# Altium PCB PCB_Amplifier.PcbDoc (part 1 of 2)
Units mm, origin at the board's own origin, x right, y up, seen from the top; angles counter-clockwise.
Board outline 88.51 x 102.08 mm, 4 copper layers (Top Layer, GND, VDD, Bottom Layer); 234 components, 166 nets, 733 pads, 363 vias.
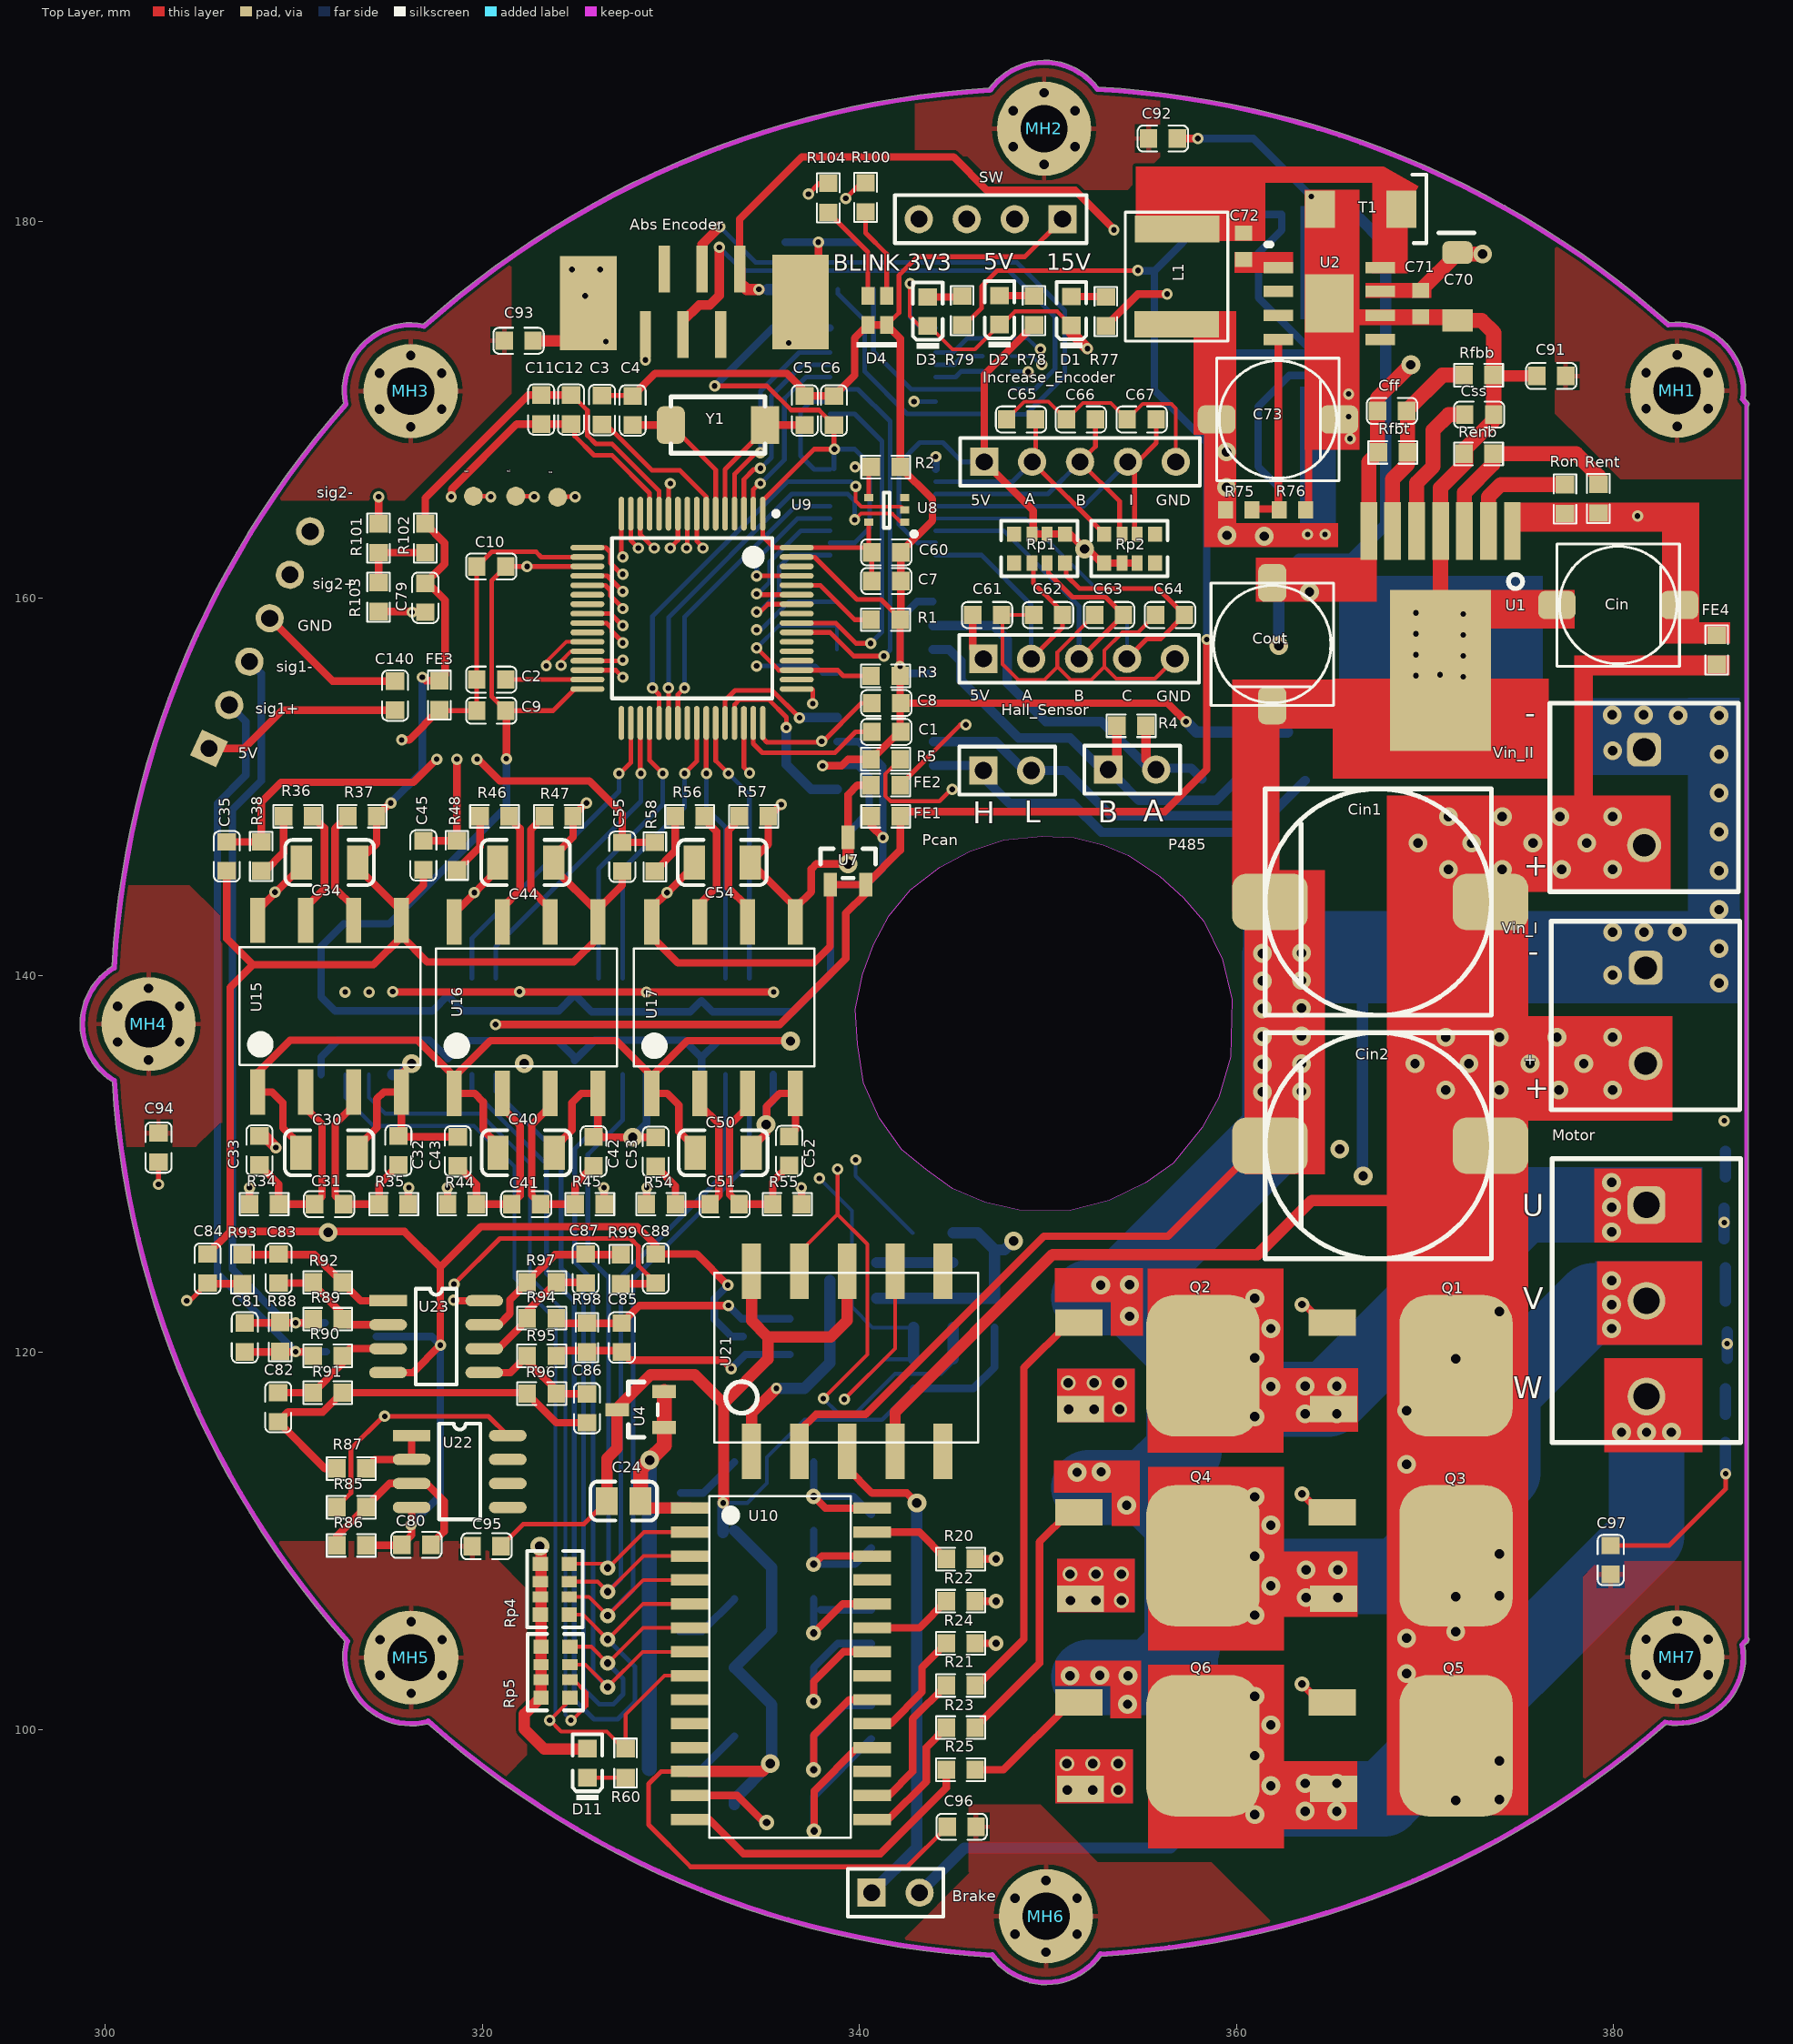
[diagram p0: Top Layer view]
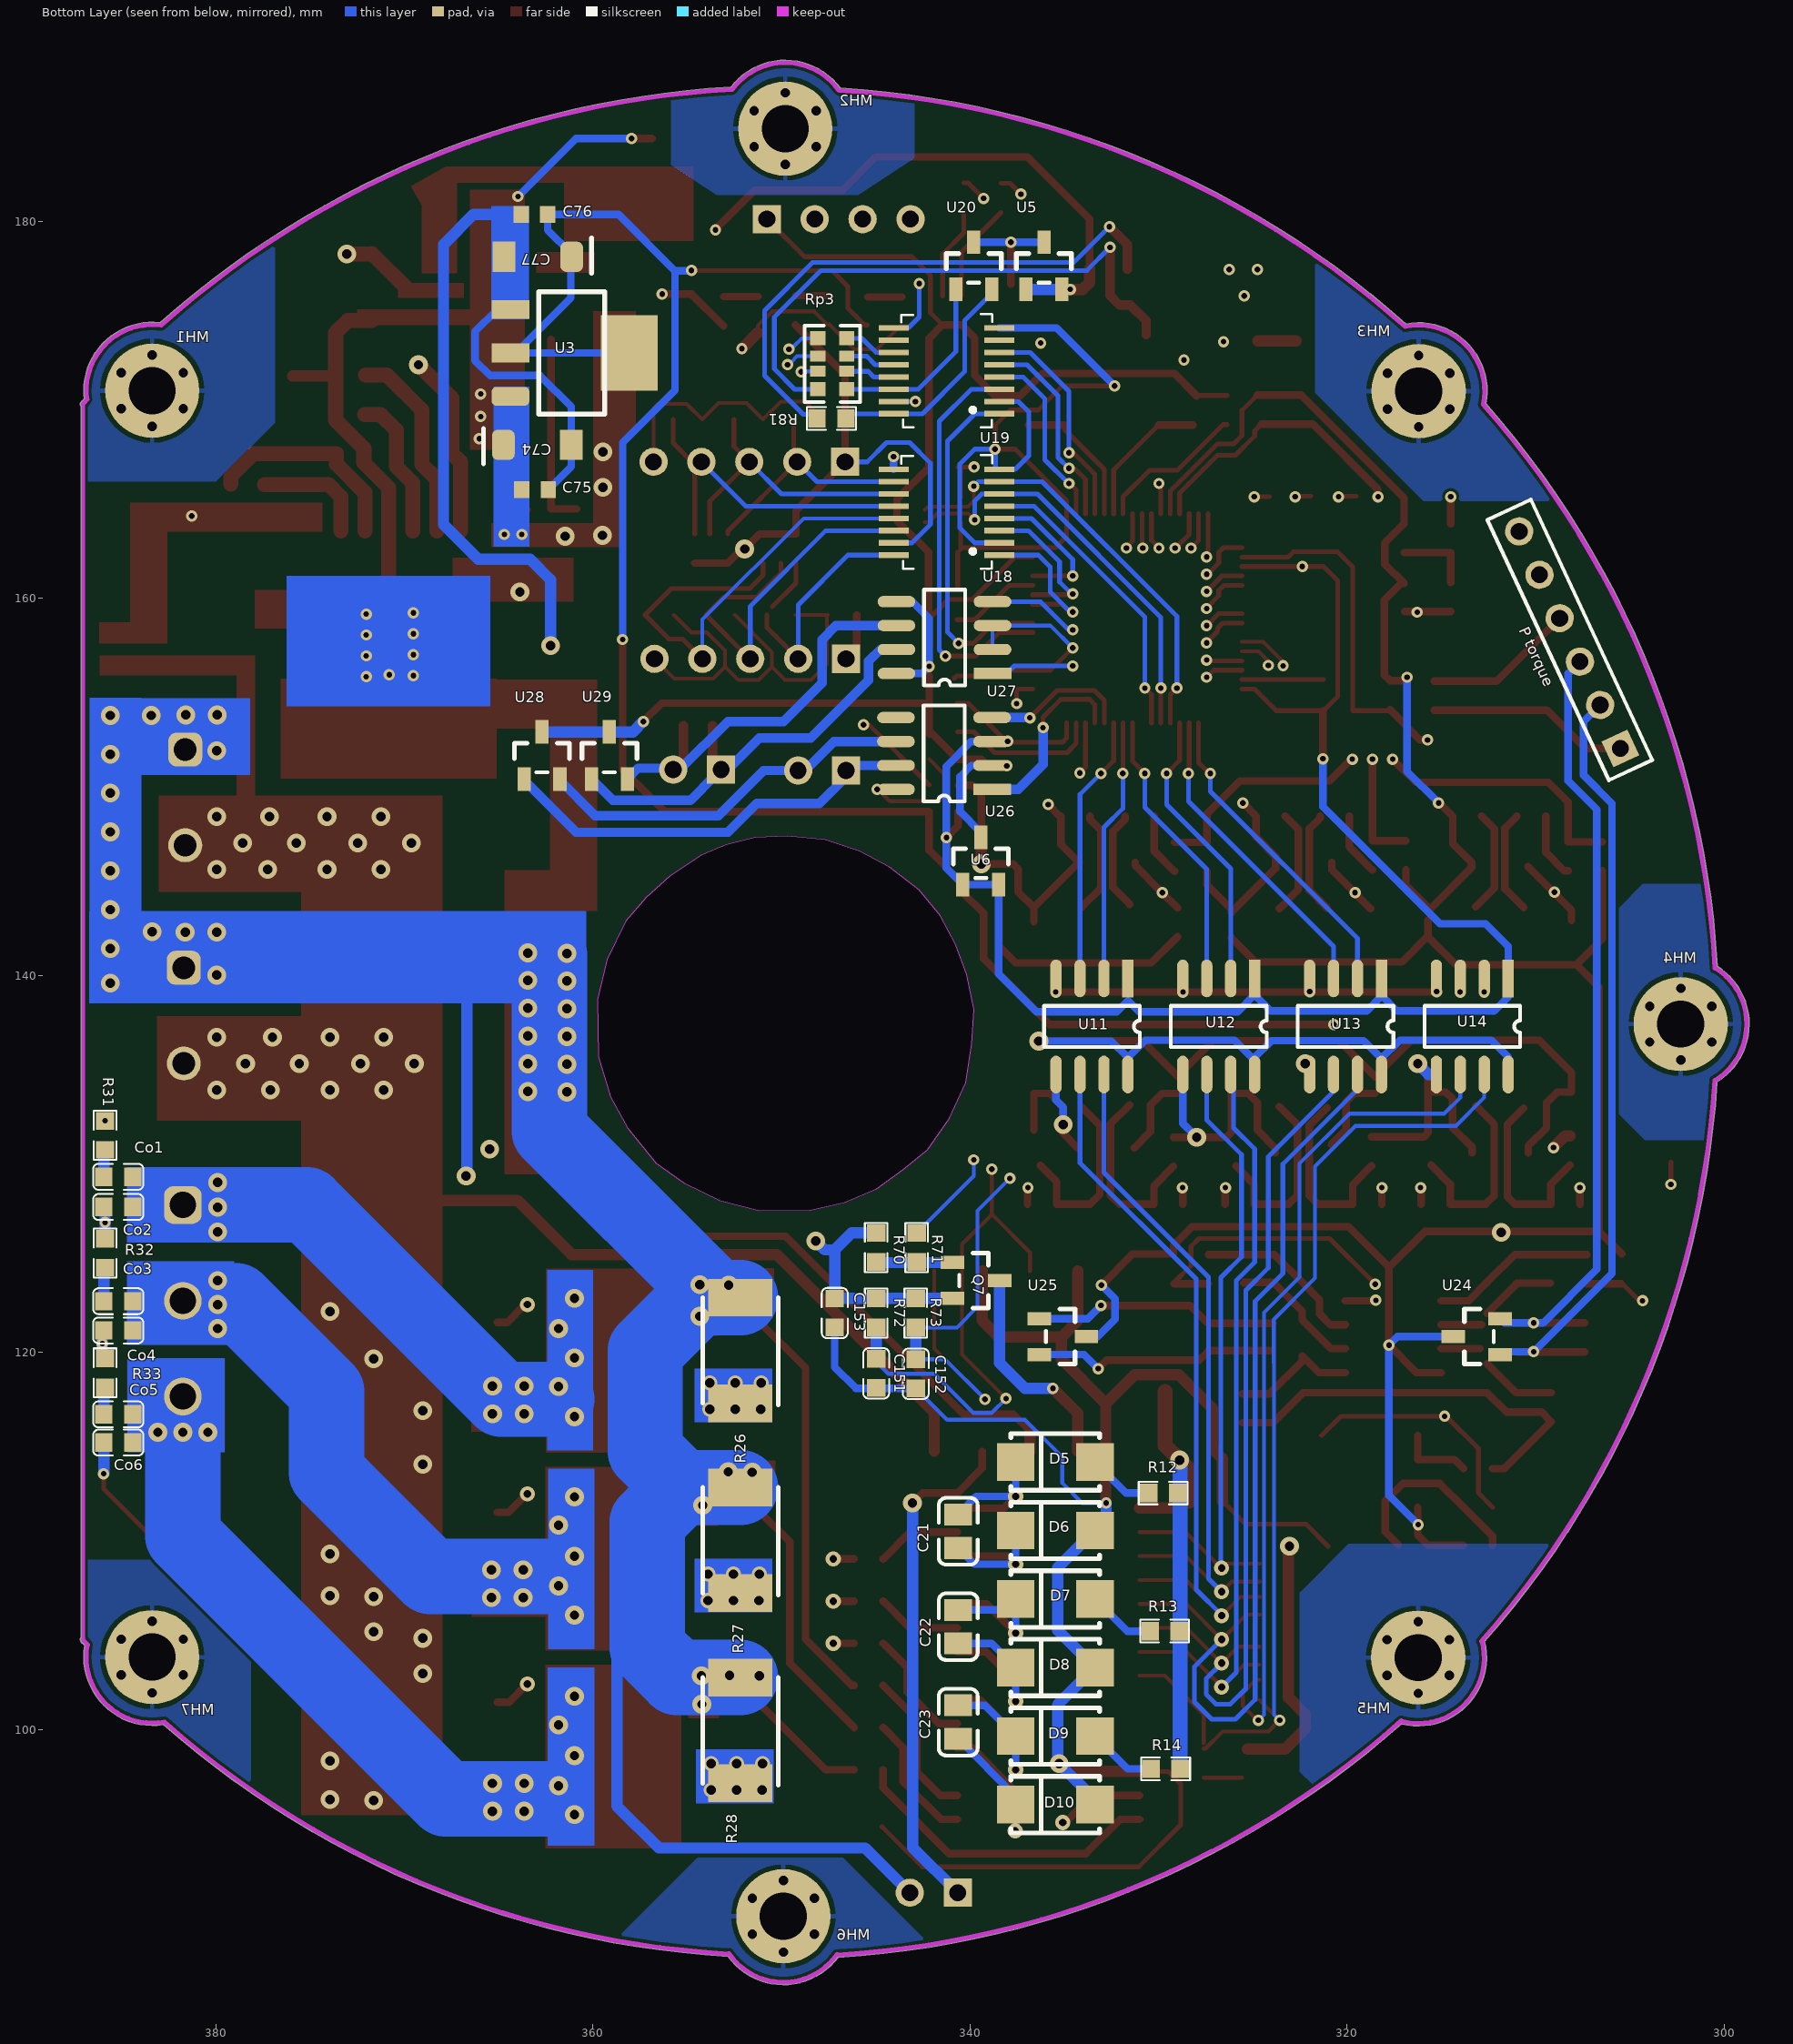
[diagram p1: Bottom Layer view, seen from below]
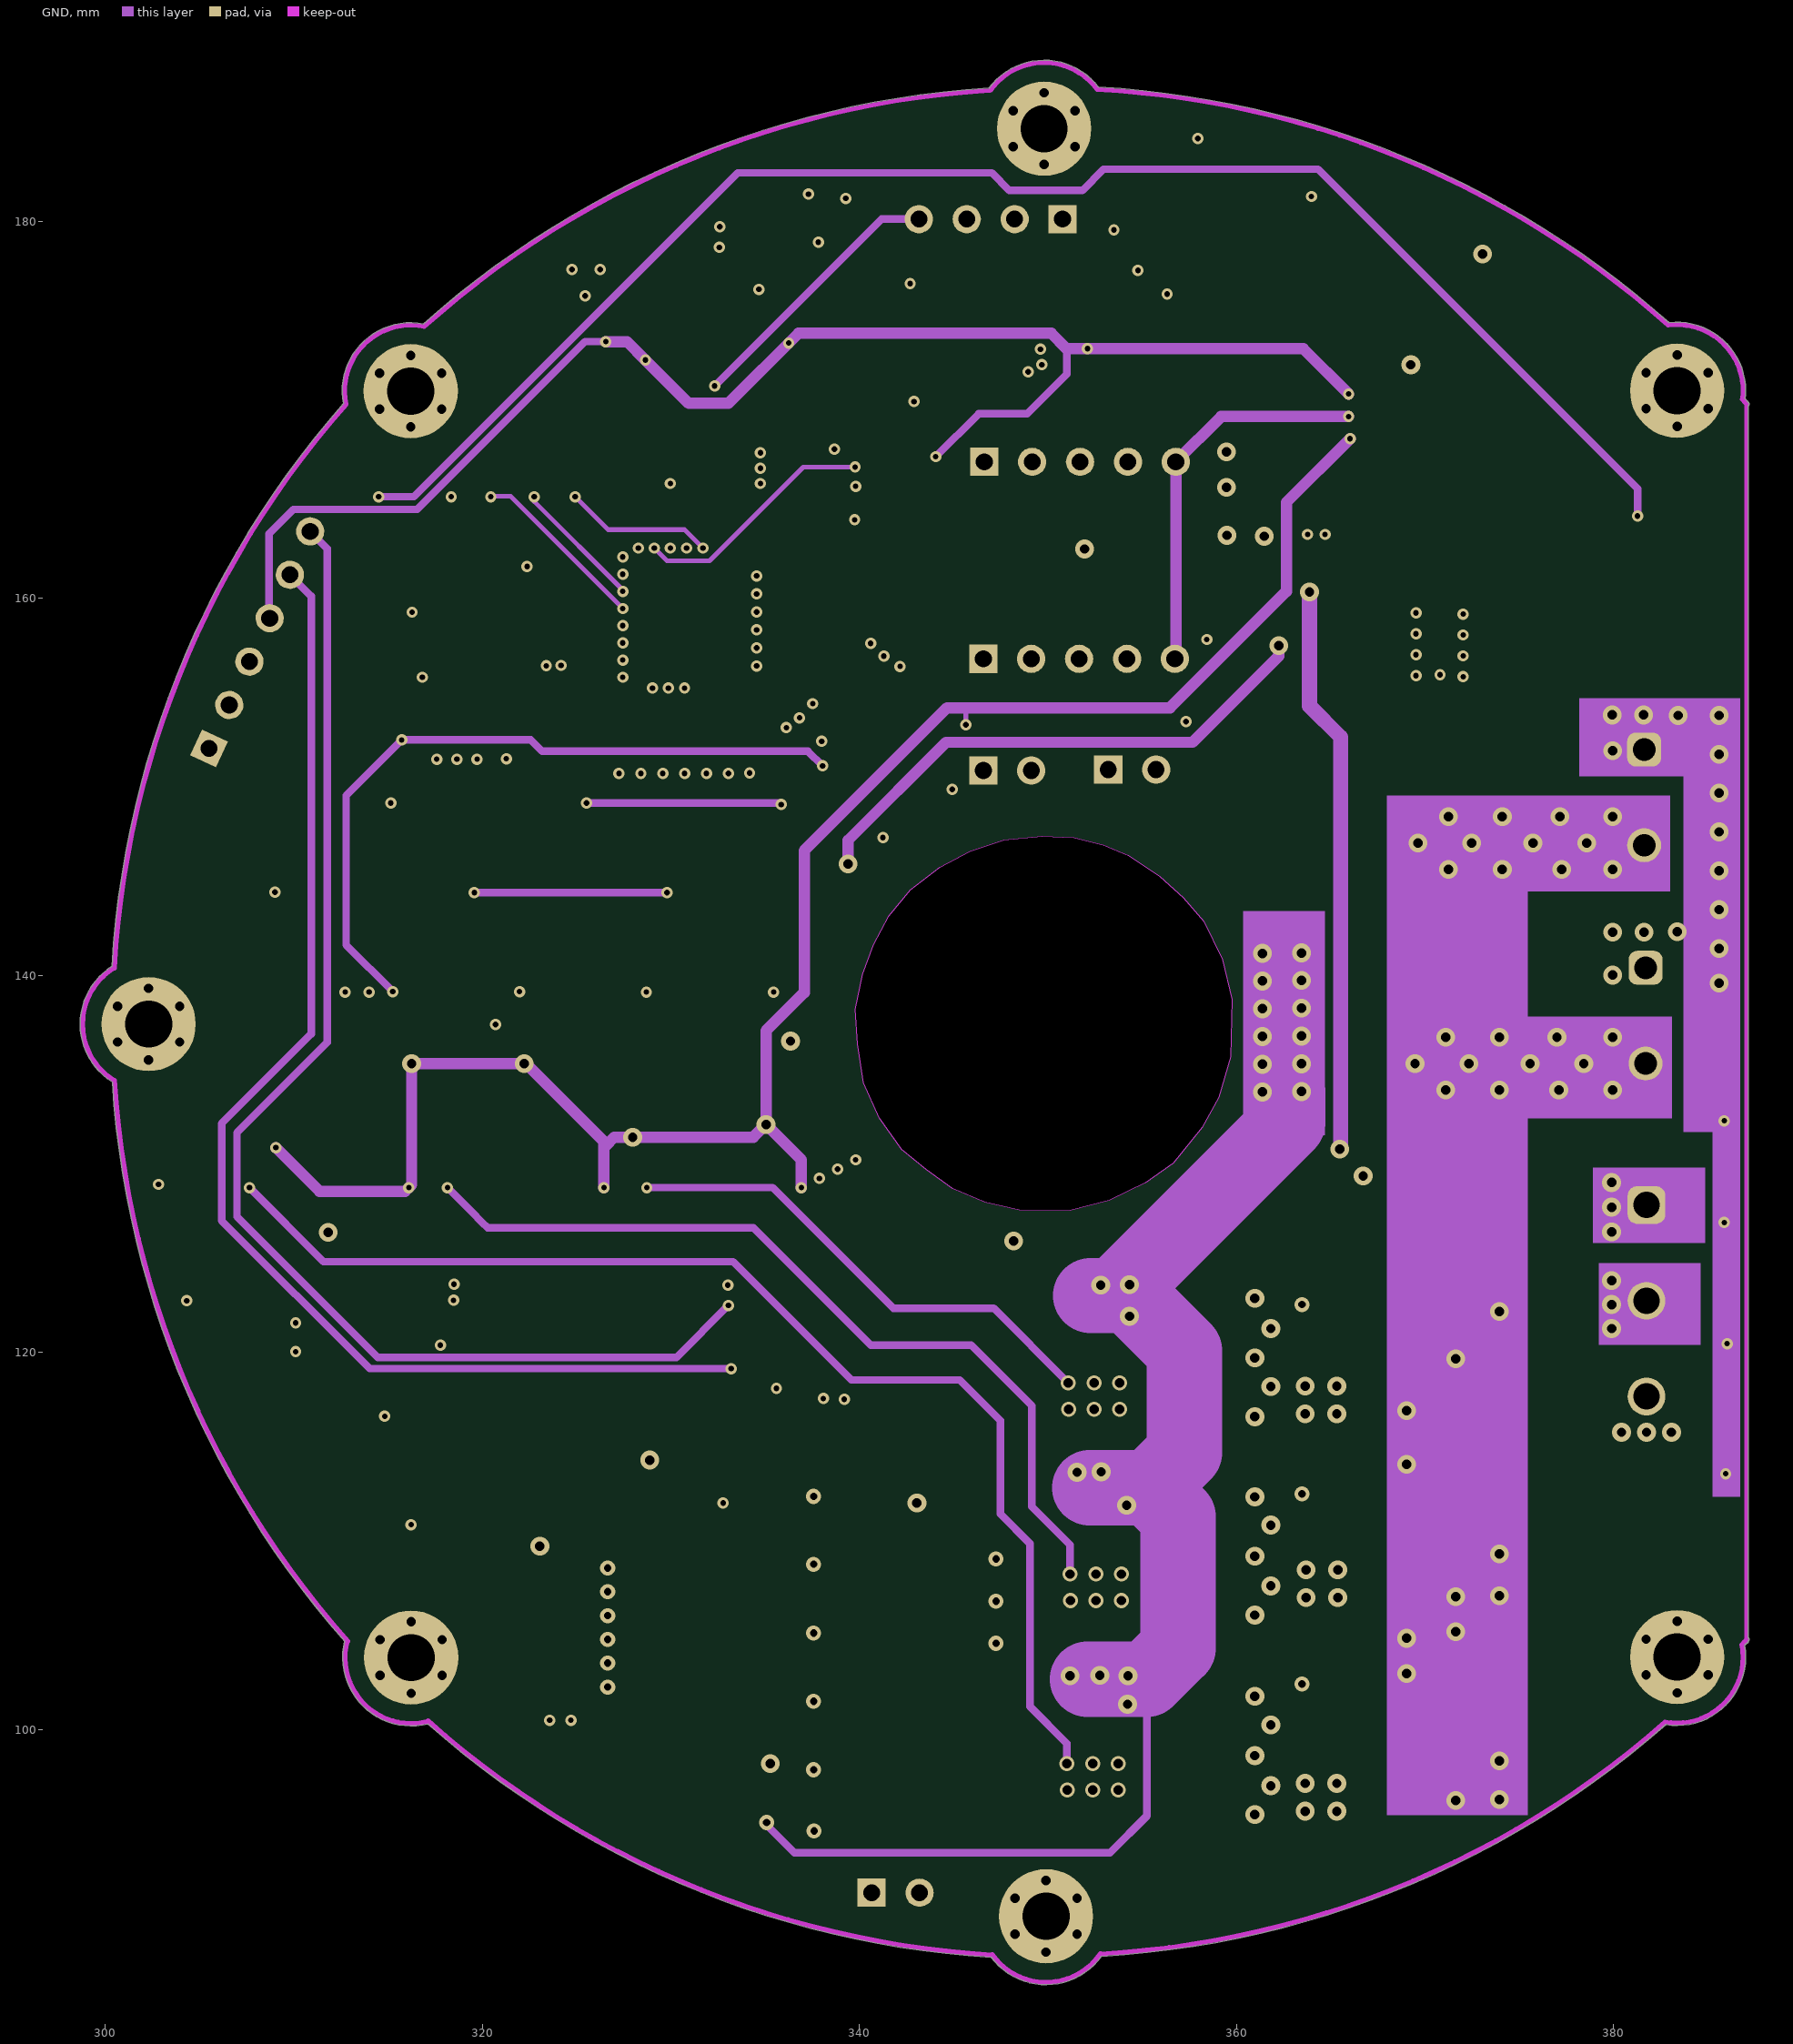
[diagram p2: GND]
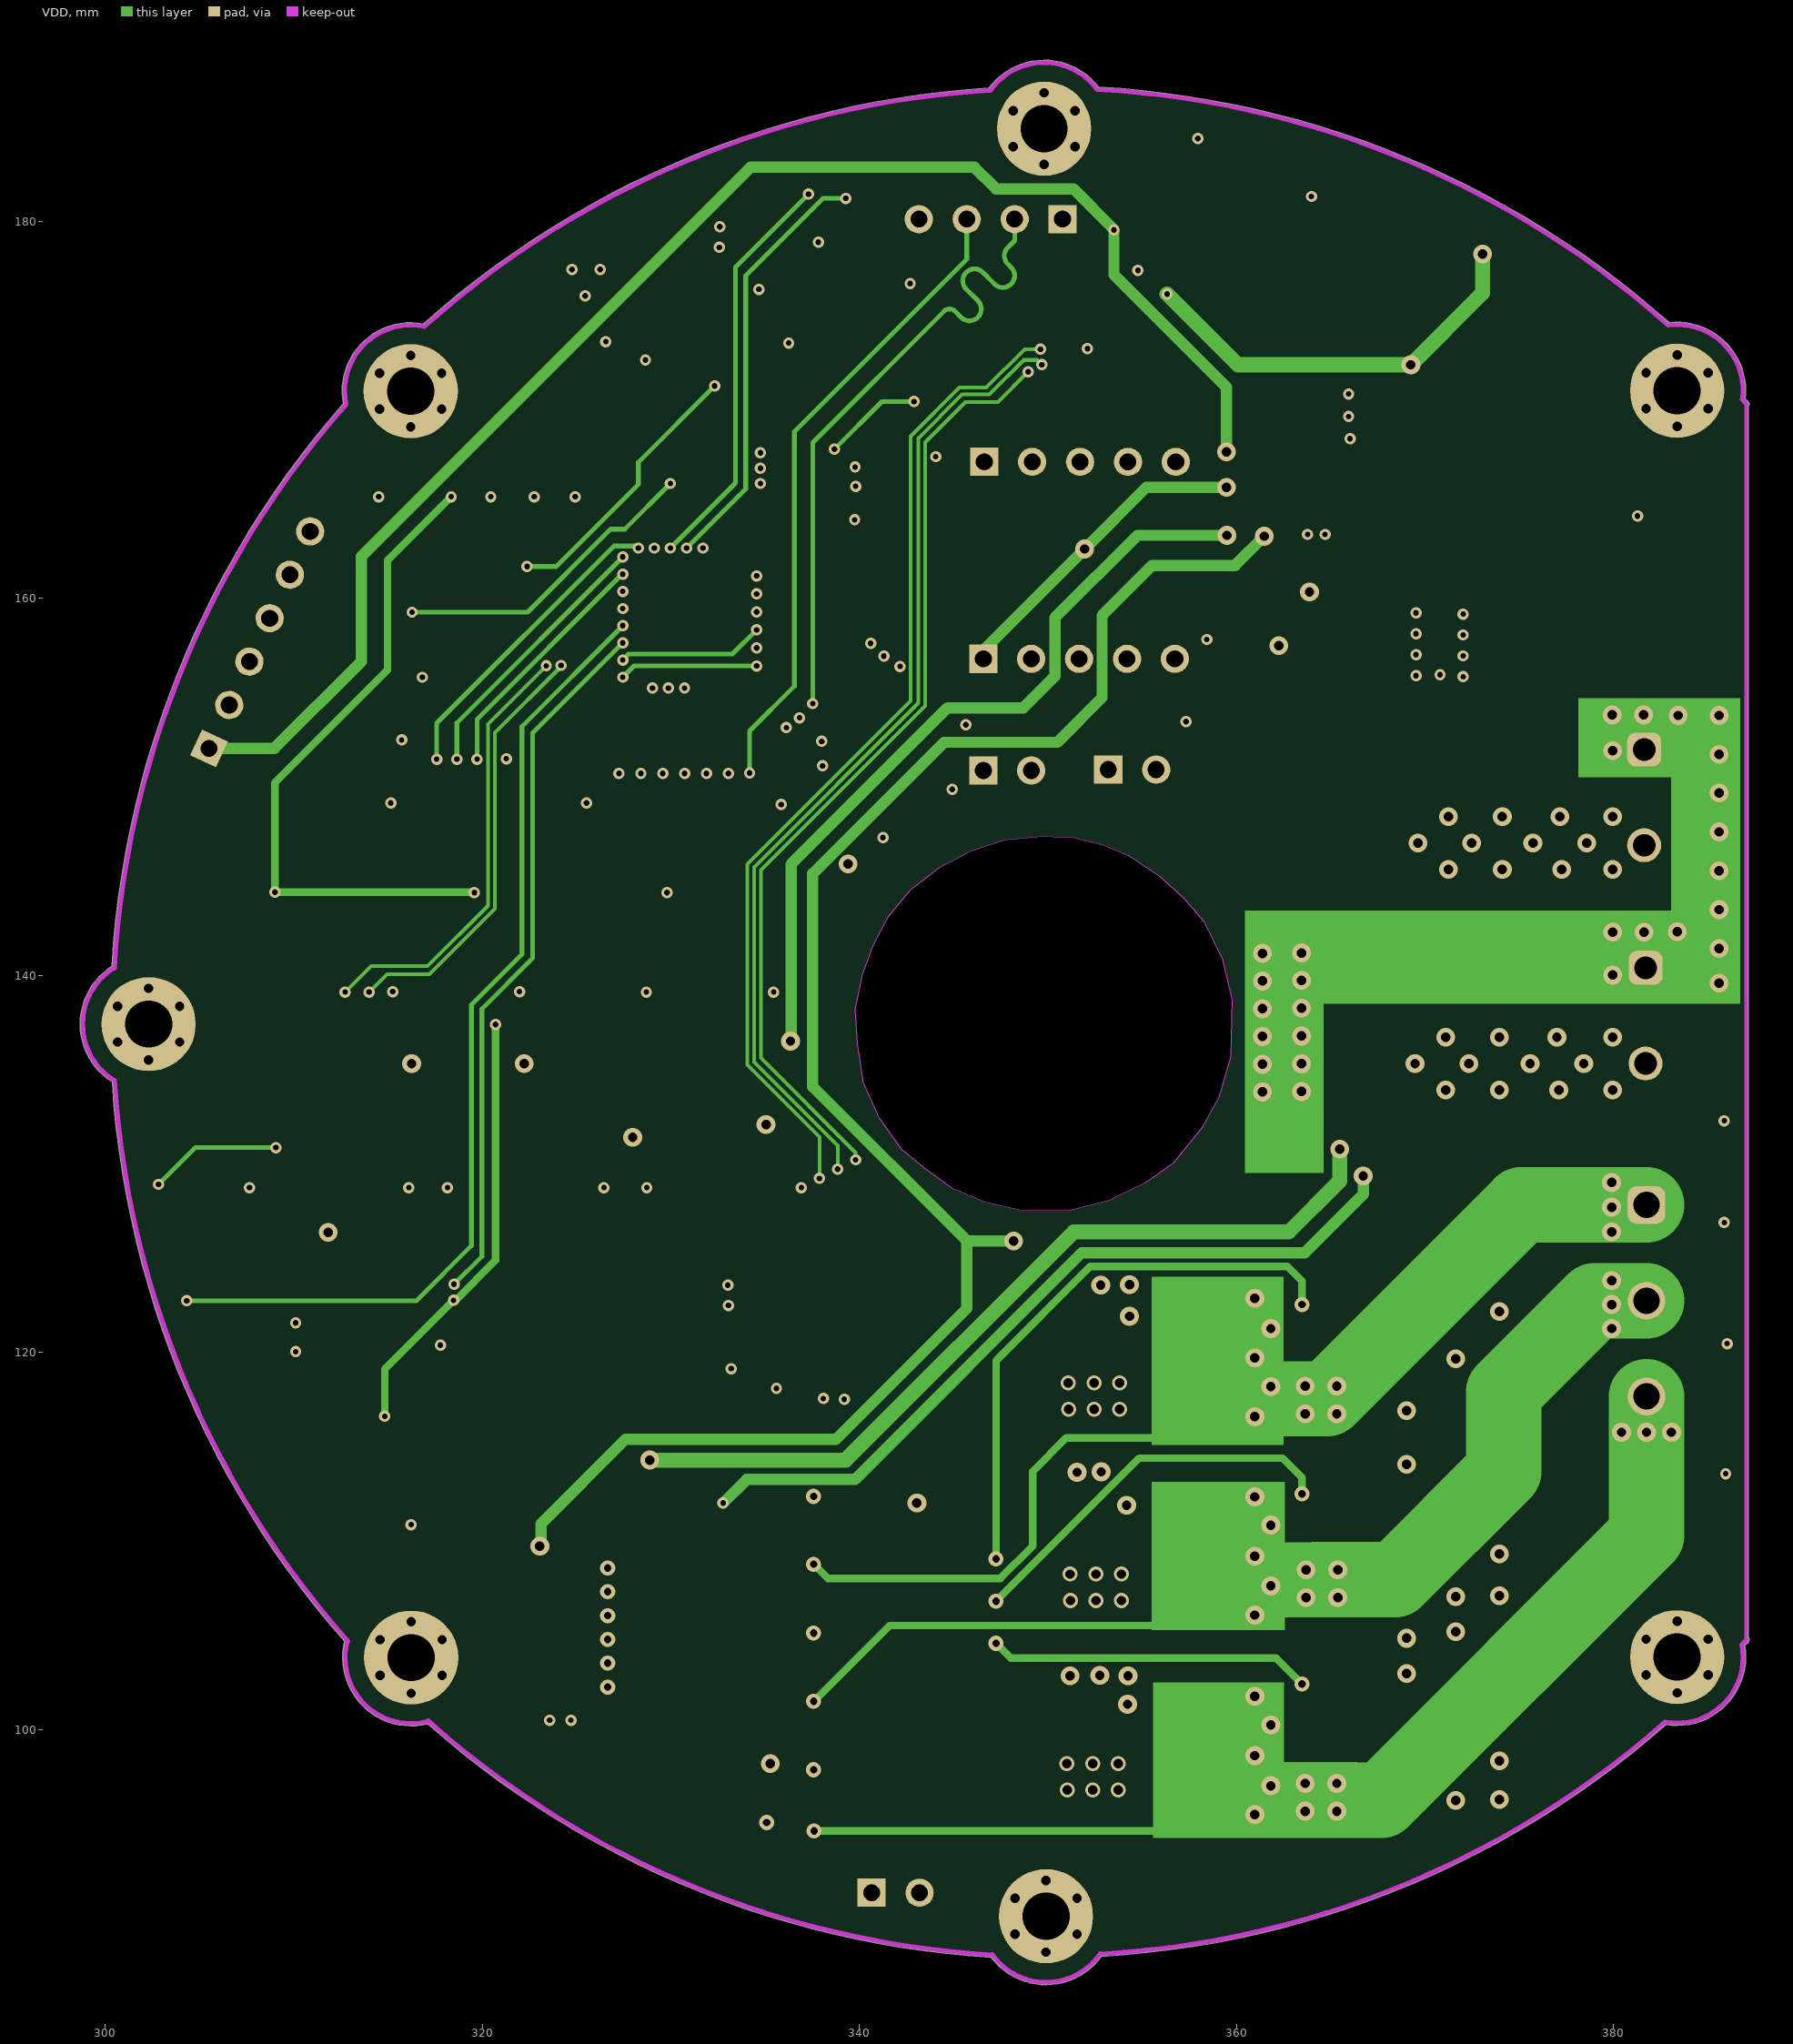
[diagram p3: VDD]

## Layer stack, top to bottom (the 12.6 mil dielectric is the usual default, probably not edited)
Top Layer: signal copper 0.0356
Dielectric: core 0.32, FR-4, Dk 4.8
GND: signal copper 0.0356
Dielectric: prepreg 0.32, FR-4, Dk 4.8
VDD: signal copper 0.0356
Dielectric: core 0.32, FR-4, Dk 4.8
Bottom Layer: signal copper 0.0356

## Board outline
317.109,100.307 ccw(c350.02,137.484) 346.997,87.925 ccw(c349.9,90.1) 352.843,87.979 ccw(c349.983,137.549) 382.781,100.272 ccw(c383.375,103.85) 387.002,103.85 ccw(c383.375,103.85) 386.949,104.467 ccw(c349.925,137.55) 387.049,104.579 ccw(c387.048,104.68) 387.148,104.68 387.148,104.691 ccw(c349.925,137.55) 387.158,104.703 ccw(c387.063,104.787) 387.19,104.787 ccw(c387.063,104.787) 387.148,104.881 387.148,170.219 ccw(c387.063,170.313) 387.19,170.313 ccw(c387.063,170.313) 387.158,170.397 ccw(c349.925,137.55) 387.141,170.418 ccw(c387.048,170.379) 387.098,170.466 ccw(c349.925,137.55) 386.978,170.601 ccw(c383.375,171.025) 387.002,171.025 ccw(c383.375,171.025) 382.949,174.627 ccw(c349.925,137.55) 352.684,187.125 ccw(c349.8,184.925) 346.88,187.077 ccw(c349.941,137.519) 316.879,174.563 ccw(c316.2,171) 312.635,170.333 ccw(c349.925,137.55) 300.36,140.49 ccw(c302.3,137.425) 300.377,134.35 ccw(c349.925,137.55) 312.702,104.69 ccw(c316.225,103.825)
cut-out: 349.675,147.4 351.4,147.325 352.925,146.925 354.25,146.375 355.925,145.275 357.175,144.125 358.275,142.875 359.25,140.85 359.75,138.725 359.7,135.7 359.05,133.55 358.175,131.925 356.65,130.05 355.175,129 353.25,128.075 351.175,127.525 348.475,127.55 346.65,127.975 344.95,128.7 343.55,129.7 342.25,130.775 341.075,132.425 340.225,134.325 339.9,136.375 339.775,138.2 340.175,140.05 340.75,141.625 341.575,143.175 342.7,144.55 344.275,145.75 345.875,146.6 347.675,147.2

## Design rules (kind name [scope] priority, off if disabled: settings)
Clearance [All] p1: gap=0.16
PolygonConnect [All] p1: connectstyle=Relief reliefconductorwidth=0.254 reliefentries=4 polygonreliefangle="90 Angle" airgapwidth=0.254
RoutingVias [All] p1: holewidth=0.711 width=1.27 viastyle="Through Hole" minholewidth=0.711 minwidth=1.27 maxholewidth=0.711 maxwidth=1.27
SolderMaskExpansion [All] p1: expansion=0.102
Width [All] p1: maxlimit=4 minlimit=0.2 preferedwidth=0.3
28 further rules are at their usual default settings.

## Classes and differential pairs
component class 电源: C70 C71 C72 C73 C74 C75 C76 C77 Cff Cin Cin1 Cin2 Cout Css D1 D2 D3 FE1 FE2 FE3 FE4 L1 R75 R76 R77 R78 R79 Renb Rent Rfbb Rfbt Ron T1 U1 U2 U3 U4 U5 U6 U7 Vin_I Vin_II
component class H桥驱动部分: C21 C22 C23 C24 C30 C31 C32 C33 C34 C35 C40 C41 C42 C43 C44 C45 C50 C51 C52 C53 C54 C55 Co1 Co2 Co3 Co4 Co5 Co6 D5 D6 D7 D8 D9 D10 D11 Motor Q1 Q2 Q3 Q4 Q5 Q6 R12 R13 R14 R20 R21 R22 R23 R24 R25 R26 R27 R28 R31 R32 R33 R34 R35 R36 R37 R38 R44 R45 R46 R47 R48 R54 R55 R56 R57 R58 R60 Rp4 Rp5 U10 U11 U12 U13 U14 U15 U16 U17
component class 主控芯片: C1 C2 C3 C4 C5 C6 C7 C8 C9 C10 C11 C12 C79 D4 R1 R2 R100 R101 R102 R103 R104 SW tp1 tp2 tp3 U8 U9 Y1
component class 通讯接口: P485 Pcan R3 R4 R5 U26 U27 U28 U29
component class 霍尔传感器以及增量编码器: C60 C61 C62 C63 C64 C65 C66 C67 C91 C92 C93 C94 C95 C96 C97 Hall_Sensor Increase_Encoder MH1 MH2 MH3 MH4 MH5 MH6 MH7 Rp1 Rp2 U18
component class 绝对编码器与抱闸: "Abs Encoder" Brake C151 C152 C153 Q7 R70 R71 R72 R73 R81 Rp3 U19 U20 U21
component class 外接力矩传感器接口: C80 C81 C82 C83 C84 C85 C86 C87 C88 C140 "P torque" R85 R86 R87 R88 R89 R90 R91 R92 R93 R94 R95 R96 R97 R98 R99 U22 U23 U24 U25

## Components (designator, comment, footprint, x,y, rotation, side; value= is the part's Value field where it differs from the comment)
"Abs Encoder" "7pin FFC" "FPC Con 6pin 1mm" 333.65,177.15 r270 top
Brake "Header 2" HDR1X2 340.65,91.35 r0 top
C1 "2.2uF (225) 10% 16V" 0603_C 341.425,152.925 r180 top
C2 "2.2uF (225) 10% 16V" 0603_C 320.475,155.7 r0 top
C3 "2.2uF (225) 10% 16V" 0603_C 326.35,170 r90 top
C4 "6pF (6R0) 0.25pF 50V" 0603_C 327.975,169.975 r90 top
C5 "6pF (6R0) 0.25pF 50V" 0603_C 337.1,169.975 r90 top
C6 "10uF (106) 10% 10V" 0603_C 338.65,169.975 r270 top
C7 "1uF (105) 10% 50V" 0603_C 341.425,160.925 r180 top
C8 "100nF (104) 10% 50V" 0603_C 341.425,154.45 r180 top
C9 "100nF (104) 10% 50V" 0603_C 320.475,154.05 r0 top
C10 "100nF (104) 10% 50V" 0603_C 320.475,161.7 r0 top
C11 "100nF (104) 10% 50V" 0603_C 323.125,170.025 r270 top
C12 "100nF (104) 10% 50V" 0603_C 324.7,170.025 r270 top
C21 "1uF (105) 10% 50V" 0805_C 340.625,110.525 r270 bottom
C22 "1uF (105) 10% 50V" 0805_C 340.625,105.462 r270 bottom
C23 "1uF (105) 10% 50V" 0805_C 340.625,100.4 r270 bottom
C24 "22uF (226) 20% 25V" 0805_C 327.5,112.125 r0 top
C30 "100nF (104) 10% 50V" 1206_C 311.875,130.6 r180 top
C31 "330pF (331) 5% 50V" 0603_C 311.875,127.875 r180 top
C32 "10pF (100) 5% 50V" 0603_C 315.55,130.725 r270 top
C33 "10pF (100) 5% 50V" 0603_C 308.175,130.725 r270 top
C34 "100nF (104) 10% 50V" 1206_C 311.9,146 r180 top
C35 "100nF (104) 10% 50V" 0603_C 306.45,146.325 r90 top
C40 "100nF (104) 10% 50V" 1206_C 322.325,130.6 r180 top
C41 "330pF (331) 5% 50V" 0603_C 322.325,127.875 r180 top
C42 "10pF (100) 5% 50V" 0603_C 325.9,130.675 r270 top
C43 "10pF (100) 5% 50V" 0603_C 318.7,130.675 r270 top
C44 "100nF (104) 10% 50V" 1206_C 322.3,146 r180 top
C45 "100nF (104) 10% 50V" 0603_C 316.875,146.375 r90 top
C50 "100nF (104) 10% 50V" 1206_C 332.775,130.6 r180 top
C51 "330pF (331) 5% 50V" 0603_C 332.85,127.875 r180 top
C52 "10pF (100) 5% 50V" 0603_C 336.275,130.7 r270 top
C53 "10pF (100) 5% 50V" 0603_C 329.2,130.65 r270 top
C54 "100nF (104) 10% 50V" 1206_C 332.725,146 r180 top
C55 "100nF (104) 10% 50V" 0603_C 327.425,146.3 r90 top
C60 "10uF (106) 10% 10V" 0603_C 341.425,162.45 r180 top
C61 "10uF (106) 10% 10V" 0603_C 346.775,159.125 r180 top
C62 "1nF (102) 10% 50V" 0603_C 350.008,159.125 r0 top
C63 "1nF (102) 10% 50V" 0603_C 353.242,159.125 r0 top
C64 "1nF (102) 10% 50V" 0603_C 356.475,159.125 r0 top
C65 "1nF (102) 10% 50V" 0603_C 348.575,169.5 r0 top
C66 "1nF (102) 10% 50V" 0603_C 351.75,169.5 r0 top
C67 "1nF (102) 10% 50V" 0603_C 354.975,169.5 r0 top
C70 "10uF 10% 16V" "Cap Tan 3015" 371.725,176.55 r270 top
C71 "4.7F 10% 50V" 1608[0603] 369.775,175.65 r90 top
C72 "10nF 16V 10%" 1608[0603] 360.375,178.675 r270 top
C73 "220uF 10V" "6.3x5.4 贴片电解电容" 358.95,166.25 r0 top
C74 "10uF 10% 16V" "Cap Tan 3015" 362.95,168.15 r180 bottom
C75 "0.1uF 50V 10%" 1608[0603] 363.075,165.775 r0 bottom
C76 "0.1uF 50V 10%" 1608[0603] 363.1,180.375 r180 bottom
C77 "10uF 10% 16V" "Cap Tan 3015" 362.925,178.125 r0 bottom
C79 "4.7uF (475) 10% 16V" 0603_C 316.975,160.04 r270 top
C80 "100nF (104) 10% 50V" 0603_C 316.5,109.8 r0 top
C81 "47pF (470) 5% 50V" 0603_C 307.4,120.805 r90 top
C82 "330pF (331) 5% 50V" 0603_C 309.175,117.1 r90 top
C83 "330pF (331) 5% 50V" 0603_C 309.2,124.46 r90 top
C84 "1nF (102) 10% 50V" 0603_C 305.425,124.46 r270 top
C85 "47pF (470) 5% 50V" 0603_C 327.4,120.8 r90 top
C86 "330pF (331) 5% 50V" 0603_C 325.55,117.05 r270 top
C87 "330pF (331) 5% 50V" 0603_C 325.475,124.46 r90 top
C88 "1nF (102) 10% 50V" 0603_C 329.2,124.46 r270 top
C91 "1nF (102) 10% 50V" 0603_C 376.7,171.8 r0 top
C92 "1nF (102) 10% 50V" 0603_C 356.1,184.4 r180 top
C93 "1nF (102) 10% 50V" 0603_C 321.925,173.675 r180 top
C94 "1nF (102) 10% 50V" 0603_C 302.825,130.875 r90 top
C95 "1nF (102) 10% 50V" 0603_C 320.225,109.725 r180 top
C96 "1nF (102) 10% 50V" 0603_C 345.425,94.85 r0 top
C97 "1nF (102) 10% 50V" 0603_C 379.85,109 r270 top
C140 "1uF (105) 10% 50V" 0603_C 315.375,154.85 r270 top
C151 "1nF (102) 10% 50V" 0603_C 344.975,118.9 r90 bottom
C152 "1nF (102) 10% 50V" 0603_C 342.875,118.875 r90 bottom
C153 "1uF (105) 10% 50V" 0603_C 347.175,122.1 r90 bottom
Cff "22nF (223) 10% 50V" 0603_C 368.25,169.95 r180 top
Cin "10uF (106) 10% 50V" "Cap 6.3x5.4" 377,156.4 r0 top
Cin1 "12.5x13.5 220uF 63V" "Cap 12.5x13.5" 367.525,143.9 r180 top
Cin2 "12.5x13.5 220uF 63V" "Cap 12.5x13.5" 367.525,130.975 r180 top
Co1 "1nF (102) 10% 50V" 0603_C 385.175,129.325 r180 bottom
Co2 "1nF (102) 10% 50V" 0603_C 385.175,127.725 r180 bottom
Co3 "1nF (102) 10% 50V" 0603_C 385.175,122.725 r180 bottom
Co4 "1nF (102) 10% 50V" 0603_C 385.175,121.175 r180 bottom
Co5 "1nF (102) 10% 50V" 0603_C 385.175,116.725 r180 bottom
Co6 "1nF (102) 10% 50V" 0603_C 385.175,115.225 r180 bottom
Cout "47uF/25V" "6.3x5.4 贴片电解电容" 358.65,160.825 r270 top
Css "4.7nF (472) 10% 50V" 0603_C 372.875,169.75 r180 top
D1 "绿灯 0603" 0603_LED_S1 351.247,175.25 r90 top
D2 "绿灯 0603" 0603_LED_S1 347.436,175.3 r90 top
D3 "绿灯 0603" 0603_LED_S1 343.625,175.225 r90 top
D4 "LED*2" 0603*2 340.45,176.05 r0 top
D5 "M7" SMA(DO-214AC)_S1 335.475,114.2 r180 bottom
D6 "M7" SMA(DO-214AC)_S1 335.475,110.565 r180 bottom
D7 "M7" SMA(DO-214AC)_S1 335.475,106.93 r180 bottom
D8 "M7" SMA(DO-214AC)_S1 335.475,103.295 r180 bottom
D9 "M7" SMA(DO-214AC)_S1 335.475,99.66 r180 bottom
D10 "M7" SMA(DO-214AC)_S1 335.475,96.025 r180 bottom
D11 "红灯 0603" 0603_LED_S1 325.575,98.225 r90 top
FE1 "1Ω (1R00) ±1%" 0603_R 341.4,148.45 r180 top
FE2 "1Ω (1R00) ±1%" 0603_R 341.39,150.1 r0 top
FE3 "1Ω (1R00) ±1%" 0603_R 317.725,154.875 r270 top
FE4 "1Ω (1R00) ±1%" 0603_R 385.475,157.275 r270 top
Hall_Sensor "" HDR1X5 346.575,156.8 r0 top
Increase_Encoder "" HDR1X5 346.625,167.25 r0 top
L1 "22uH" "L 5x5mm" 356.85,174.6 r90 top
MH1 "M2 hole" "M2 Hole" 383.375,171.025 r0 top
MH2 "M2 hole" "M2 Hole" 349.8,184.925 r0 top
MH3 "M2 hole" "M2 Hole" 316.2,171 r0 top
MH4 "M2 hole" "M2 Hole" 302.3,137.425 r0 top
MH5 "M2 hole" "M2 Hole" 316.225,103.825 r0 top
MH6 "M2 hole" "M2 Hole" 349.9,90.1 r0 top
MH7 "M2 hole" "M2 Hole" 383.375,103.85 r0 top
Motor "Header 3" "3P 5mm" 381.75,122.75 r90 top
P485 "Header 2" HDR1X2 353.2,150.925 r0 top
"P torque" "Header 6" HDR1X6 305.5,152.05 r65 bottom
Pcan "Header 2" HDR1X2 346.575,150.875 r0 top
Q1 "IRFR3806PbF" TO-252AA 371.65,119.3 r270 top
Q2 "IRFR3806PbF" TO-252AA 358.225,119.3 r270 top
Q3 "IRFR3806PbF" TO-252AA 371.65,109.225 r270 top
Q4 "IRFR3806PbF" TO-252AA 358.225,109.225 r270 top
Q5 "IRFR3806PbF" TO-252AA 371.65,99.15 r270 top
Q6 "IRFR3806PbF" TO-252AA 358.225,99.15 r270 top
Q7 "MMBT5401 2L" SOT-23(SOT-23-3) 339.675,123.825 r0 bottom
R1 "10KΩ (1002) ±1%" 0603_R 341.39,158.875 r180 top
R2 "10KΩ (1002) ±1%" 0603_R 341.4,166.975 r180 top
R3 "10KΩ (1002) ±1%" 0603_R 341.39,155.9 r0 top
R4 "10KΩ (1002) ±1%" 0603_R 354.425,153.25 r0 top
R5 "0Ω (0R0) ±1%" 0603_R 341.39,151.475 r180 top
R12 "10Ω (10R0) ±1%" 0603_R 329.75,112.55 r0 bottom
R13 "10Ω (10R0) ±1%" 0603_R 329.675,105.225 r0 bottom
R14 "10Ω (10R0) ±1%" 0603_R 329.625,97.925 r0 bottom
R20 "100Ω (1000) ±1%" 0603_R 345.375,109.05 r0 top
R21 "100Ω (1000) ±1%" 0603_R 345.375,102.345 r0 top
R22 "100Ω (1000) ±1%" 0603_R 345.375,106.815 r0 top
R23 "100Ω (1000) ±1%" 0603_R 345.375,100.11 r0 top
R24 "100Ω (1000) ±1%" 0603_R 345.375,104.58 r0 top
R25 "100Ω (1000) ±1%" 0603_R 345.375,97.875 r0 top
R26 "0.01Ω (1000) ±1%" 2512 352.275,120.25 r0 bottom
R27 "0.01Ω (1000) ±1%" 2512 352.275,110.175 r0 bottom
R28 "100Ω (1000) ±1%" 2512 352.275,100.1 r0 bottom
R31 "100Ω (1000) ±1%" 0603_R 385.875,131.525 r270 bottom
R32 "100Ω (1000) ±1%" 0603_R 385.875,125.275 r270 bottom
R33 "100Ω (1000) ±1%" 0603_R 385.875,118.925 r270 bottom
R34 "10Ω (10R0) ±1%" 0603_R 308.425,127.875 r0 top
R35 "10Ω (10R0) ±1%" 0603_R 315.3,127.875 r180 top
R36 "10Ω (10R0) ±1%" 0603_R 310.225,148.45 r180 top
R37 "10Ω (10R0) ±1%" 0603_R 313.625,148.45 r0 top
R38 "10Ω (10R0) ±1%" 0603_R 308.275,146.325 r90 top
R44 "10Ω (10R0) ±1%" 0603_R 318.925,127.875 r0 top
R45 "10Ω (10R0) ±1%" 0603_R 325.7,127.875 r180 top
R46 "10Ω (10R0) ±1%" 0603_R 320.65,148.45 r180 top
R47 "10Ω (10R0) ±1%" 0603_R 324.05,148.45 r0 top
R48 "10Ω (10R0) ±1%" 0603_R 318.65,146.375 r90 top
R54 "10Ω (10R0) ±1%" 0603_R 329.475,127.875 r0 top
R55 "10Ω (10R0) ±1%" 0603_R 336.175,127.875 r180 top
R56 "10Ω (10R0) ±1%" 0603_R 331,148.45 r180 top
R57 "10Ω (10R0) ±1%" 0603_R 334.4,148.45 r0 top
R58 "10Ω (10R0) ±1%" 0603_R 329.15,146.3 r90 top
R60 "2.2KΩ (2201) ±1%" 0603_R 327.6,98.225 r90 top
R70 "100KΩ (1003) ±1%" 0603_R 344.975,125.575 r90 bottom
R71 "4.7KΩ (4701) ±1%" 0603_R 342.825,125.575 r270 bottom
R72 "27KΩ (2702) ±1%" 0603_R 344.975,122.1 r90 bottom
R73 "27KΩ (2702) ±1%" 0603_R 342.875,122.1 r90 bottom
R75 "10K 1%" 1608[0603] 360.125,164.7 r180 top
R76 "3.24k 1%" 1608[0603] 362.975,164.7 r180 top
R77 "1KΩ (1001) ±1%" 0603_R 353.075,175.225 r270 top
R78 "1KΩ (1001) ±1%" 0603_R 349.264,175.275 r270 top
R79 "1KΩ (1001) ±1%" 0603_R 345.453,175.275 r270 top
R81 "220Ω (2200) ±1%" 0603_R 347.35,169.55 r0 bottom
R85 "10KΩ (1002) ±1%" 0603_R 313.05,111.8 r180 top
R86 "10KΩ (1002) ±1%" 0603_R 313.05,109.775 r180 top
R87 "47Ω (47R0) ±1%" 0603_R 313.05,113.85 r180 top
R88 "47KΩ (4702) ±1%" 0603_R 309.275,120.83 r90 top
R89 "11KΩ (1102) ±1%" 0603_R 311.8,121.775 r0 top
R90 "11KΩ (1102) ±1%" 0603_R 311.8,119.825 r0 top
R91 "10KΩ (1002) ±1%" 0603_R 311.8,117.875 r180 top
R92 "10KΩ (1002) ±1%" 0603_R 311.8,123.725 r0 top
R93 "2KΩ (2001) ±1%" 0603_R 307.275,124.425 r270 top
R94 "11KΩ (1102) ±1%" 0603_R 323.15,121.825 r0 top
R95 "11KΩ (1102) ±1%" 0603_R 323.15,119.825 r0 top
R96 "10KΩ (1002) ±1%" 0603_R 323.15,117.825 r180 top
R97 "10KΩ (1002) ±1%" 0603_R 323.15,123.725 r180 top
R98 "47KΩ (4702) ±1%" 0603_R 325.55,120.8 r90 top
R99 "2KΩ (2001) ±1%" 0603_R 327.35,124.425 r270 top
R100 "1KΩ (1001) ±1%" 0603_R 340.325,181.275 r90 top
R101 "82KΩ (8202) ±1%" 0603_R 314.5,163.2 r90 top
R102 "10KΩ (1002) ±1%" 0603_R 316.975,163.2 r270 top
R103 "10KΩ (1002) ±1%" 0603_R 314.5,160.075 r90 top
R104 "1KΩ (1001) ±1%" 0603_R 338.35,181.25 r90 top
Renb "270KΩ (2703) ±1%" 0603_R 372.84,167.675 r0 top
Rent "270KΩ (2703) ±1%" 0603_R 379.2,165.3 r90 top
Rfbb "1.8KΩ (1801) ±1%" 0603_R 372.84,171.85 r180 top
Rfbt "36KΩ (3602) ±1%" 0603_R 368.3,167.75 r180 top
Ron "270KΩ (2703) ±1%" 0603_R 377.425,165.275 r90 top
Rp1 "1KΩ (102) ±5%" 0603_Rx4 349.55,162.65 r0 top
Rp2 "1KΩ (102) ±5%" 0603_Rx4 354.325,162.65 r180 top
Rp3 "1KΩ (102) ±5%" 0603_Rx4 347.3,172.45 r90 bottom
Rp4 "4.7KΩ (472) ±5%" 0603_Rx4 323.85,107.45 r90 top
Rp5 "4.7KΩ (472) ±5%" 0603_Rx4 323.875,103.05 r90 top
SW "Header 4" HDR1X4 350.775,180.125 r180 top
T1 "SS12" "DO214 SS12" 364.425,180.65 r0 top
tp1 "test point" testPoint 321.775,165.425 r0 top
tp2 "test point" testPoint 319.525,165.425 r90 top
tp3 "test point" testPoint 324,165.375 r90 top
U1 "LMZ14201" LMZ14201H 370.825,163.575 r180 top
U2 "TPS5430" SOIC8 364.925,175.65 r0 top
U3 "LM1117-3.3" "SOT-223 LM1117-3.3" 364.375,173.025 r270 bottom
U4 "PSM712-LF-T7" SOT-23(SOT-23-3) 328.4,116.975 r0 top
U5 "PSM712-LF-T7" SOT-23(SOT-23-3) 336.075,177.65 r270 bottom
U6 "PSM712-LF-T7" SOT-23(SOT-23-3) 339.425,146.075 r270 bottom
U7 "PSM712-LF-T7" SOT-23(SOT-23-3) 339.4,146.075 r270 top
U8 "NC7S86" "5Lead SC70" 341.45,164.7 r90 top
U9 "STM32F405RGT6" STM-LQFP64_N 331.125,158.95 r270 top
U10 "IR2130" "28-Lead SOIC(wide body)" 331,111.75 r0 top
U11 "Adum1200" SOP-8 331.625,139.85 r270 bottom
U12 "Adum1200" SOP-8 324.9,139.85 r270 bottom
U13 "Adum1200" SOP-8 318.175,139.85 r270 bottom
U14 "ADUM 1201" SOP-8 311.45,139.85 r270 bottom
U15 "AMC1200-Q1" SOP_4.85mm 311.9,138.325 r90 top
U16 "AMC1200-Q1" SOP_4.85mm 322.325,138.25 r90 top
U17 "AMC1200-Q1" SOP_4.85mm 332.8,138.25 r90 top
U18 "TXB0106" "TSSOP 16PIN" 338.45,162.3 r0 bottom
U19 "TXB0106" "TSSOP 16PIN" 338.45,169.8 r0 bottom
U20 "PSM712-LF-T7" SOT-23(SOT-23-3) 339.8,177.65 r270 bottom
U21 "TQ2SA-5V" TQ2SA 334.275,124.325 r0 top
U22 "TLV2772_D_8" SOP-8 316.25,115.6 r0 top
U23 "TLV2772_D_8" SOP-8 315,122.75 r0 top
U24 "PSM712-LF-T7" SOT-23(SOT-23-3) 313.125,120.85 r180 bottom
U25 "PSM712-LF-T7" SOT-23(SOT-23-3) 335.075,120.85 r0 bottom
U26 "VP230" SOP-8 338.825,149.875 r0 bottom
U27 "SP3485" SOP-8 338.8,156.025 r0 bottom
U28 "PSM712-LF-T7" SOT-23(SOT-23-3) 362.7,151.675 r270 bottom
U29 "PSM712-LF-T7" SOT-23(SOT-23-3) 359.125,151.675 r270 bottom
Vin_I "Header 2" "2P 5mm" 381.7,137.875 r270 top
Vin_II "Header 2" "2P 5mm" 381.625,149.45 r270 top
Y1 "XTAL" "XTAL CPX53GB" 332.5,167.7 r0 top

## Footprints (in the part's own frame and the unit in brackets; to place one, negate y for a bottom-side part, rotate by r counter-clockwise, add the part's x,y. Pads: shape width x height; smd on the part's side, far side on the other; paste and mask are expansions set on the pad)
"2P 5mm" [mm]
  rrect50% 1.8x1.8 hole 1.2: 1(-2.54,0)
  round 1.8 hole 1.2: 2(2.54,0)
  silkscreen extent -5,-5 5,5, body extent -5.32,-5.19 5.33,5.2, height 14.21
"3P 5mm" [mm]
  rrect50% 2x2 hole 1.4: 1(5.08,0)
  round 2 hole 1.4: 2(0,0) 3(-5.08,0)
  silkscreen extent -7.52,-5 7.54,5
"5Lead SC70" [mm] "NC7S86 1.25mm wide"
  rect 0.4x0.5 smd: 1(-0.65,-0.95) 2(0,-0.95) 3(0.65,-0.95) 4(0.65,0.95) 5(-0.65,0.95)
  silkscreen extent -1.4,-1.58 0.92,0.15, body extent -1,-0.6 0.97,0.63, height 1.3
"6.3x5.4 贴片电解电容" [mm]
  rrect50% 2x1.5 smd: 1(0,3.25) 2(6.5,3.25)
  silkscreen extent 0,0 6.5,6.5, body extent -0.05,0.05 6.45,6.55, height 8
"28-Lead SOIC(wide body)" [mm] "IR2136STRPBF 三相驱动桥"
  rect 2x0.6 smd: 1(0,0) 2(0,-1.27) 3(0,-2.54) 4(0,-3.81) 5(0,-5.08) 6(0,-6.35) 7(0,-7.62) 8(0,-8.89) 9(0,-10.16) 10(0,-11.43) 11(0,-12.7) 12(0,-13.97) 13(0,-15.24) 14(0,-16.51) 15(9.675,-16.51) 16(9.675,-15.24) 17(9.675,-13.97) 18(9.675,-12.7) 19(9.675,-11.43) 20(9.675,-10.16) 21(9.675,-8.89) 22(9.675,-7.62) 23(9.675,-6.35) 24(9.675,-5.08) 25(9.675,-3.81) 26(9.675,-2.54) 27(9.675,-1.27) 28(9.675,0)
  silkscreen extent 1.05,-17.47 8.55,0.63, body extent -0.5,-17.27 10,0.73, height 2.5
0603*2 [mm] "˫ɫLED"
  rect 0.7x0.93 smd: 1(1,0) 2(0,0) 3(1,-1.54) 4(0,-1.54)
  silkscreen extent -0.6,-2.75 1.55,-2.45, body extent -0.4,-1.57 1.4,0.03, height 0.6
0603_C [mm]
  rect 0.93x0.98 smd: 1(-0.77,0) 2(0.77,0)
  silkscreen extent -1.33,-0.69 1.34,0.69, body extent -0.8,-0.4 0.8,0.4, height 0.3
0603_LED_S1 [mm]
  rect 0.93x0.98 smd: A(0.77,0) K(-0.77,0)
  silkscreen extent -1.98,-0.79 1.54,0.79, body extent -0.8,-0.4 0.8,0.4, height 0.6
0603_R [mm]
  rect 0.93x0.98 smd: 1(-0.77,0) 2(0.77,0)
  silkscreen extent -1.3,-0.6 1.3,0.6, body extent -0.85,-0.4 0.85,0.4, height 0.56
0603_Rx4 [mm]
  rect 0.75x0.8 smd mask+0.051: 1(-1.35,-0.77) 4(1.35,-0.77) 5(1.35,0.77) 8(-1.35,0.77)
  rect 0.58x0.8 smd mask+0.051: 2(-0.4,-0.77) 3(0.4,-0.77) 6(0.4,0.77) 7(-0.4,0.77)
  silkscreen extent -2.02,-1.47 2.02,1.47, body extent -1.6,-0.8 1.6,0.8, height 0.55
0805_C [mm]
  rect 1.16x1.47 smd: 1(-0.89,0) 2(0.89,0)
  silkscreen extent -1.77,-1.04 1.77,1.04, body extent -1,-0.63 1,0.63, height 0.77
1206_C [mm]
  rect 1.13x1.8 smd: 1(-1.49,0) 2(1.49,0)
  silkscreen extent -2.36,-1.2 2.35,1.2, body extent -1.6,-0.81 1.6,0.79, height 1
1608[0603] [mm] "Chip Capacitor, Body 1.6x0.8mm, IPC High Density"
  rect 0.8x0.9 smd: 1(-0.7,0) 2(0.7,0)
  body extent -0.87,-0.48 0.87,0.48, height 1.3
2512 [mm]
  rect 3.4x2 smd: 1(-0.101,-2.667) 2(-0.101,2.933)
  silkscreen extent -2.1,-2.67 1.9,3.03, body extent -1.6,-2.77 1.4,3.23, height 0.5
"Cap 6.3x5.4" [mm] "贴片电解电容"
  rrect50% 2x1.5 smd: 1(0,3.25) 2(6.5,3.25)
  silkscreen extent 0,0 6.5,6.5, body extent -0.05,0.05 6.45,6.55, height 8
"Cap 12.5x13.5" [mm] "SMD Aluminum Electrolytic Cap"
  rrect50% 4x3 smd: 1(-5.95,0) 2(5.75,0)
  silkscreen extent -6,-6 6,6, body extent -4.15,-4.15 4.15,4.15, height 10.5
"Cap Tan 3015" [mm]
  rrect50% 1.2x1.6 smd: 1(-1.8,0)
  rect 1.2x1.6 smd: 2(1.8,0)
  silkscreen extent -2.85,-1 -2.85,0.87
"DO214 SS12" [mm] "二极管 SS14"
  rect 1.6x2 smd: 1(0,0) 2(4.325,0)
  silkscreen extent 4.91,-1.8 5.65,1.83, body extent -0.45,-1.3 4.75,1.3, height 2.4
"FPC Con 6pin 1mm" [mm] "立式插座"
  rect 2.5x0.6 smd: 1(-0.325,0) 2(3.15,-1) 3(-0.325,-2) 4(3.15,-3) 5(-0.325,-4) 6(3.15,-5)
  rect 5x3 smd: 7(1.425,3.225) 7(1.475,-8.025)
  body extent -1.63,-9 4.43,4, height 5.7
HDR1X2 [mm] "Connector; Header; 2 Position"
  rect 1.5x1.5 hole 0.9: 1(0,0)
  round 1.5 hole 0.9: 2(2.54,0)
  silkscreen extent -1.27,-1.27 3.81,1.27
HDR1X4 [mm] "Connector; Header; 4 Position"
  rect 1.5x1.5 hole 0.9: 1(0,0)
  round 1.5 hole 0.9: 2(2.54,0) 3(5.08,0) 4(7.62,0)
  silkscreen extent -1.27,-1.27 8.89,1.27
HDR1X5 [mm] "Connector; Header; 5 Position"
  rect 1.5x1.5 hole 0.9: 1(0,0)
  round 1.5 hole 0.9: 2(2.54,0) 3(5.08,0) 4(7.62,0) 5(10.16,0)
  silkscreen extent -1.27,-1.27 11.43,1.27
HDR1X6 [mm] "Connector; Header; 6 Position"
  rect 1.5x1.5 hole 0.9: 1(0,0)
  round 1.5 hole 0.9: 2(2.54,0) 3(5.08,0) 4(7.62,0) 5(10.16,0) 6(12.7,0)
  silkscreen extent -1.27,-1.27 13.97,1.27
"L 5x5mm" [mm] "5x5mm电感"
  rect 1.4x4.5 smd: 1(-0.05,0.025) 2(5,0)
  silkscreen extent -0.95,-2.7 5.9,2.75, body extent -0.48,-2.4 5.38,2.37, height 3.6
LMZ14201H [mm] "LMZ14201H 1A SIMPLE SWITCHER,Power Module for High Output Voltage"
  rect 0.89x3.06 smd: 1(-3.81,0) 2(-2.54,0) 3(-1.27,0) 4(0,0) 5(1.27,0) 6(2.54,0) 7(3.81,0)
  rect 5.35x8.54 smd: 8(0,7.4)
  silkscreen extent -4.35,2.3 -3.6,3.05, body extent -5.12,-1.07 5.08,12.73, height 4.5
"M2 Hole" [mm] "孔径2.5mm"
  round 5 hole 2.5: 1(0,0)
SMA(DO-214AC)_S1 [mm]
  rect 2x2 smd: 1(2.1,0) 2(-2.1,0)
  silkscreen extent -2.35,-1.5 2.35,1.5
SOIC8 [mm] "TPS5430"
  rect 1.55x0.6 smd: 1(-2.7,1.905) 2(-2.7,0.635) 3(-2.7,-0.635) 4(-2.7,-1.905) 5(2.7,-1.905) 6(2.7,-0.635) 7(2.7,0.635) 8(2.7,1.905)
  rect 2.6x3.1 smd: 9(0,0)
  silkscreen extent -3.3,3.13 -3.1,3.13, body extent -2.9,-2.5 2.9,2.5, height 2.11
SOP-8 [mm]
  rect 2x0.6 smd: 1(0,0)
  oval 2x0.6 smd: 2(0,-1.27) 3(0,-2.54) 4(0,-3.81) 5(5.1,-3.81) 6(5.1,-2.54) 7(5.1,-1.27) 8(5.1,0)
  silkscreen extent 1.46,-4.45 3.64,0.63, body extent -0.32,-4.4 5.48,0.6, height 2.11
SOP_4.85mm [mm] "全差动隔离放大器"
  rect 2.4x0.8 smd: 1(-4.5,3.81) 2(-4.5,1.27) 3(-4.5,-1.27) 4(-4.5,-3.81) 5(4.6,-3.81) 6(4.6,-1.27) 7(4.6,1.27) 8(4.6,3.81)
  silkscreen extent -3.08,-4.82 3.18,4.77, body extent -5.25,-4.7 5.45,4.8, height 4.85
SOT-23(SOT-23-3) [mm]
  rect 1.25x0.7 smd: 1(1.25,-0.95) 2(1.25,0.95) 3(-1.25,0)
  silkscreen extent -0.65,-1.46 0.9,1.46, body extent -1.5,-1.5 1.5,1.5, height 1.3
"SOT-223 LM1117-3.3" [mm]
  rrect50% 1x2 smd: 1(2.3,0)
  rect 1x2 smd: 2(0,0) 3(-2.3,0)
  rect 4x3 smd: 4(0,6.3)
  silkscreen extent -3.25,1.5 3.25,5, body extent -3.25,0.03 3.25,7.33, height 1.6
STM-LQFP64_N [mm] "Thin QFP, 64-Leads, Body 10x10mm, Pitch 0.5mm, IPC Medium Density"
  oval 1.8x0.3 smd: 1(-5.55,3.75) 2(-5.55,3.25) 3(-5.55,2.75) 4(-5.55,2.25) 5(-5.55,1.75) 6(-5.55,1.25) 7(-5.55,0.75) 8(-5.55,0.25) 9(-5.55,-0.25) 10(-5.55,-0.75) 11(-5.55,-1.25) 12(-5.55,-1.75) 13(-5.55,-2.25) 14(-5.55,-2.75) 15(-5.55,-3.25) 16(-5.55,-3.75) 33(5.55,-3.75) 34(5.55,-3.25) 35(5.55,-2.75) 36(5.55,-2.25) 37(5.55,-1.75) 38(5.55,-1.25) 39(5.55,-0.75) 40(5.55,-0.25) 41(5.55,0.25) 42(5.55,0.75) 43(5.55,1.25) 44(5.55,1.75) 45(5.55,2.25) 46(5.55,2.75) 47(5.55,3.25) 48(5.55,3.75)
  oval 0.3x1.8 smd: 17(-3.75,-5.55) 18(-3.25,-5.55) 19(-2.75,-5.55) 20(-2.25,-5.55) 21(-1.75,-5.55) 22(-1.25,-5.55) 23(-0.75,-5.55) 24(-0.25,-5.55) 25(0.25,-5.55) 26(0.75,-5.55) 27(1.25,-5.55) 28(1.75,-5.55) 29(2.25,-5.55) 30(2.75,-5.55) 31(3.25,-5.55) 32(3.75,-5.55) 49(3.75,5.55) 50(3.25,5.55) 51(2.75,5.55) 52(2.25,5.55) 53(1.75,5.55) 54(1.25,5.55) 55(0.75,5.55) 56(0.25,5.55) 57(-0.25,5.55) 58(-0.75,5.55) 59(-1.25,5.55) 60(-1.75,5.55) 61(-2.25,5.55) 62(-2.75,5.55) 63(-3.25,5.55) 64(-3.75,5.55)
  silkscreen extent -5.67,-4.25 4.25,4.58, body extent -5,-5 5,5, height 1.6
testPoint [mm]
  round 1 smd: 1(0,0)
TO-252AA [mm] "IRFR3806PbF N沟道MOSFET"
  rect 1.4x2.5 smd: 1(-2.3,-6.575) 3(2.29,-6.5)
  rrect50% 7.5x6 smd: 2(0,0)
  body extent -3.3,-7.44 3.3,2.49, height 2.2
TQ2SA [mm] "双通道继电器"
  rect 1x2.94 smd: 1(0,-9.56) 2(2.54,-9.56) 3(5.08,-9.56) 4(7.62,-9.56) 5(10.16,-9.56) 6(10.16,0) 7(7.62,0) 8(5.08,0) 9(2.54,0) 10(0,0)
  silkscreen extent -1.97,-9.1 12.03,-0.1, body extent -1.95,-9.17 12.05,-0.17, height 5.6
"TSSOP 16PIN" [mm] "TXB0106 tssop"
  rect 1.6x0.3 smd: 1(0,0) 2(0,-0.65) 3(0,-1.3) 4(0,-1.95) 5(0,-2.6) 6(0,-3.25) 7(0,-3.9) 8(0,-4.55) 9(5.6,-4.55) 10(5.6,-3.9) 11(5.6,-3.25) 12(5.6,-2.6) 13(5.6,-1.95) 14(5.6,-1.3) 15(5.6,-0.65) 16(5.6,0)
  silkscreen extent 0.38,-5.3 5.2,0.72
"XTAL CPX53GB" [mm]
  rrect50% 1.5x2 smd: 1(-2.5,1.5)
  rect 1.5x2 smd: 2(2.5,1.5)
  silkscreen extent -2.5,0 2.5,3, body extent -2.48,0 2.52,3, height 0.85

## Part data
"Abs Encoder": library part "Header 7", "1mm 7pin FPC插座 下贴翻盖"
Brake: "电磁抱闸接口"
C1 C2 C3: library part "0603 2.2uF (225) 10% 16V", "贴片电容"
C4 C5: library part "0603 6pF (6R0) 0.25pF 50V", "贴片电容"
C6 C60 C61: library part "0603 10uF (106) 10% 10V", "贴片电容"
C7 C140 C153: library part "0603 1uF (105) 10% 50V", "贴片电容"
C8 C9 C10 C11 C12 C35 C45 C55 C80: library part "0603 100nF (104) 10% 50V", "贴片电容"
C21 C22 C23: library part "0805 1uF (105) 10% 50V", "贴片电容"
C24: library part "0805 22uF (226) 20% 25V", "贴片电容"
C30 C34 C40 C44 C50 C54: library part "1206 100nF (104) 10% 50V", "贴片电容"
C31 C41 C51 C82 C83 C86 C87: library part "0603 330pF (331) 5% 50V", "贴片电容"
C32 C33 C42 C43 C52 C53: library part "0603 10pF (100) 5% 50V", "贴片电容"
C62 C63 C64 C65 C66 C67 C84 C88 C91 C92 C93 C94 C95 C96 C97 C151 C152 Co1 Co2 Co3 Co4 Co5 Co6: library part "0603 1nF (102) 10% 50V", "贴片电容"
C70: library part CAPACITOR, "贴片钽电容"
C71 C72: library part Cap, "贴片电容"
C73: library part "CAPACITOR POL", "表贴电解电容 5x5.9"
C74 C77: library part "Cap Pol3", "贴片钽电容"
C75 C76: library part "Cap Semi", "贴片电容"
C79: library part "0603 4.7uF (475) 10% 16V", "贴片电容"
C81 C85: library part "0603 47pF (470) 5% 50V", "贴片电容"
Cff: library part "0603 22nF (223) 10% 50V", "贴片电容"
Cin: library part "1206 10uF (106) 10% 50V", "贴片电容"
Cin1 Cin2: library part "Cap Pol1", "表贴电解电容"
Cout: library part "Cap Pol1", "贴片电解电容"
Css: library part "0603 4.7nF (472) 10% 50V", "贴片电容"
D1 D2 D3: library part "0603 绿灯", "发光二极管"
D4: library part "0603*2 LED"
D5 D6 D7 D8 D9 D10: library part "SMA(DO-214AC) M7", "二极管"
D11: library part "0603 红灯", "发光二极管"
FE1 FE2 FE3 FE4: library part "0603 1Ω (1R00) 1%", "贴片电阻"
Hall_Sensor Increase_Encoder: library part "Header 5", "Header, 5-Pin"
L1: library part INDUCTOR_SLF, "贴片电感"
Motor: "电机绕组接线"
P485 Pcan Vin_I Vin_II: "Header, 2-Pin"
"P torque": "Header, 6-Pin"
Q1 Q2 Q3 Q4 Q5 Q6: library part NMOS-2, "N-Channel Power MOSFET 60V 43A"
Q7: library part "SOT-23 MMBT5401 2L", "三极管"
R1 R2 R3 R4 R85 R86 R91 R92 R96 R97 R102 R103: library part "0603 10KΩ (1002) 1%", "贴片电阻"
R5: library part "0603 0Ω (0R0) 1%", "贴片电阻"
R12 R13 R14 R34 R35 R36 R37 R38 R44 R45 R46 R47 R48 R54 R55 R56 R57 R58: library part "0603 10Ω (10R0) 1%", "贴片电阻"
R20 R21 R22 R23 R24 R25 R26 R27 R28 R31 R32 R33: library part "0603 100Ω (1000) 1%", "贴片电阻"
R60: library part "0603 2.2KΩ (2201) 1%", "贴片电阻"
R70: library part "0603 100KΩ (1003) 1%", "贴片电阻"
R71: library part "0603 4.7KΩ (4701) 1%", "贴片电阻"
R72 R73: library part "0603 27KΩ (2702) 1%", "贴片电阻"
R75 R76: library part res1, "贴片电阻"
R77 R78 R79 R100 R104: library part "0603 1KΩ (1001) 1%", "贴片电阻"
R81: library part "0603 220Ω (2200) 1%", "贴片电阻"
R87: library part "0603 47Ω (47R0) 1%", "贴片电阻"
R88 R98: library part "0603 47KΩ (4702) 1%", "贴片电阻"
R89 R90 R94 R95: library part "0603 11KΩ (1102) 1%", "贴片电阻"
R93 R99: library part "0603 2KΩ (2001) 1%", "贴片电阻"
R101: library part "0603 82KΩ (8202) 1%", "贴片电阻"
Renb Rent Ron: library part "0603 270KΩ (2703) 1%", "贴片电阻"
Rfbb: library part "0603 1.8KΩ (1801) 1%", "贴片电阻"
Rfbt: library part "0603 36KΩ (3602) 1%", "贴片电阻"
Rp1 Rp2 Rp3: library part "0603*4  1KΩ (102) 5%", "贴片排阻"
Rp4 Rp5: library part "0603*4  4.7KΩ (472) 5%", "贴片排阻"
SW: "Header, 4-Pin"
T1: library part B360A, "贴片肖特基二极管"
U1: "LMZ14201H 1A SIMPLE SWITCHER Power Module for High Output Voltage"
U2: library part TPS543x, "降压芯片"
U4 U5 U6 U7 U20 U24 U25 U28 U29: library part PSM712-LF-T7_[C32677], "TVS"
U8: "单路异或门"
U9: "ARM Cortex-M4 32-bit MCU+FPU, 210 DMIPS, 1024 kB Flash, 192 kB Internal RAM, 51 I/Os, 64-pin LQFP, -40 to 85 degC, Tray"
U10: "3-phase bridge driver"
U11 U12 U13: library part "ADUM 1200", "数字隔离器 1MHz"
U14: "数字隔离器 1MHz"
U15 U16 U17: library part AMC1200, "全差动隔离放大器 固定增益8倍 隔离电压4000V"
U18 U19: "6-Bit Bidirectional Level-Shifting and Voltage Translator  With Auto-Direction Sensing and ±15-kV ESD Protection"
U21: library part TQ2SA, "双通道继电器"
U22 U23: "双路运放"
Y1: "贴片无源晶振"

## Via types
v1: diameter 0.6, hole 0.3, Top Layer to Bottom Layer, 150 vias
v2: diameter 1, hole 0.5, Top Layer to Bottom Layer, 134 vias
v3: diameter 0.8, hole 0.5, Top Layer to Bottom Layer, 60 vias
v4: diameter 0.8, hole 0.4, Top Layer to Bottom Layer, 19 vias

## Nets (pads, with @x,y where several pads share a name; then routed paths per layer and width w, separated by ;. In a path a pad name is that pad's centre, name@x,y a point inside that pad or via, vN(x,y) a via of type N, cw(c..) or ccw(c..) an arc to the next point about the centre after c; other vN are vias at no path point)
3V3_A: C11.2 C12.2 C34.2 C44.2 C54.2 C76.2 C77.1 FE1.1 R79.2 R85.2 U3.2 U3.4 U7.1 U7.2 U9.13 U15.8 U16.8 U17.8 U22.8 U23.8 | length 233.7
  Top Layer w0.25: R85.2@312.28,111.8 313.03,112.55 313.03,114.905 314.75,116.625 320.325,116.625 U22.8@321.35,115.6 ; C12.2@324.55,169.255 324.9,168.905 324.9,168.625 325.925,167.6 326.875,167.6 328.875,165.6 U9.13@328.875,164.5 ; R79.2@345.453,174.505 345.58,174.505 346.475,175.4 346.475,176.55 347.325,177.4 v1(354.775,177.4)
  Top Layer w0.4: U15.8@308.09,142.925 308.09,143.465 C34.2@310.41,145.785 ; v1@318.375,165.4 318.375,165.8 321.83,169.255 C12.2@324.55,169.255 ; v1@318.5,122.75 U23.8@320.1,122.75 ; U16.8@318.75,143.55 320.81,145.61 C44.2@320.81,146 ; v1(320.7,137.4) 335.775,137.4 339.275,140.9 339.275,143.3 340.35,144.375 U7.2@340.35,144.825 ; U17.8@328.99,142.06 330.375,140.675 337.575,140.675 338.45,141.55 U7.1@338.45,144.825 U7.2@340.35,144.825 ; U17.8@328.99,143.59 v1(329.8,144.4) 331.235,145.835 C54.2@331.235,146 ; v1(358.425,157.825) 358.425,150.925 356.2,148.7 342.17,148.7 342.17,146.645 U7.2@340.35,144.825
  GND w0.4: v1(319.575,144.4) v1(329.8,144.4)
  VDD w0.4: v1(314.825,116.625) 314.825,119.125 v1(318.475,122.775) 318.583,122.775 320.7,124.892 v1(320.7,137.4) ; v1(318.35,165.4) 314.975,162.025 314.975,156.2 309,150.225 v1(309,144.425) v1@319.55,144.425
  Bottom Layer w0.4: v1@354.8,177.375 355.65,177.375 ; U3.4@358.075,173.025 U3.2@364.1,173.025 ; v1(358.425,157.825) 358.425,168.275 355.65,171.05 355.65,177.375 ; C77.1@361.125,178.125 361.125,178.275 362.4,179.55 C76.2@362.4,180.375 358.65,180.375 355.65,177.375 ; C77.1@361.175,178.075 361.175,175.95 U3.2@364.1,173.025 ; U3.2@364.375,173.025 U3.2@364.1,173.025
3V3_A_GND: C11.1 C12.1 C34.1 C35.1 C44.1 C45.1 C54.1 C55.1 C74.2 C75.1 C76.1 C77.2 C79.1 C80.1 C84.1 C88.1 FE2.1 FE3.1 R37.2 R47.2 R57.2 R86.1 R102.1 U3.3 U7.3 U9.12 U15.5 U16.5 U17.5 U22.4 U23.4 U24.3 U25.3 | length 260.6
  Top Layer w0.25: C12.1@324.755,170.795 325.575,169.975 325.575,168.647 326.022,168.2 326.875,168.2 329.375,165.7 U9.12@329.375,164.5
  Top Layer w0.4: C84.1@305.425,125.23 306.62,126.425 ; C35.1@306.45,145.555 306.45,141.95 307.825,140.575 ; R86.1@313.82,109.775 315.705,109.775 C80.1@315.73,109.8 316.25,110.32 U22.4@316.25,111.79 ; U23.4@315,118.94 316.315,118.94 v1(317.775,120.4) 317.775,124.525 ; v1@315.145,149.2 R37.2@314.395,148.45 314.395,147.005 C34.1@313.39,146 313.39,145.735 U15.5@315.6,143.525 ; U15.5@315.71,142.925 U15.5@315.71,142.09 ; U15.5@315.71,143.635 316.875,144.8 C45.1@316.875,145.605 ; v1(316.82,155.825) 317,155.645 FE3.1@317.725,155.645 318.025,155.945 318.025,159.9 317.115,160.81 C79.1@316.975,160.81 318,161.835 318,162.945 R102.1@316.975,163.97 316.975,165.325 322.445,170.795 C12.1@324.755,170.795 ; v1(325.525,149.155) R47.2@324.82,148.45 324.82,147.345 323.79,146.315 C44.1@323.79,146 323.79,145.685 U16.5@326.135,143.34 ; U16.5@326.135,142.01 324.85,140.725 317.075,140.725 U15.5@315.71,142.09 ; U16.5@326.135,143.51 327.425,144.8 C55.1@327.425,145.53 ; v1(333.025,123.575) 331.37,125.23 C88.1@329.2,125.23 329.2,125.7 328.225,126.675 319.925,126.675 317.775,124.525 ; v1(335.85,149.075) 335.225,148.45 R57.2@335.17,148.45 335.17,146.955 C54.1@334.215,146 U17.5@336.61,143.605 ; U17.5@336.61,142.85 U17.5@336.61,143.605 ; v2(339.4,145.925) 337.725,145.925 337.45,145.65 337.45,144.445 U17.5@336.61,143.605 ; U7.3@339.4,147.325 339.4,149.6 339.9,150.1 FE2.1@340.62,150.1 ; 306.62,126.425 315.875,126.425 317.775,124.525 ; 306.62,126.425 306.62,139.37 307.825,140.575 ; 307.825,140.575 314.225,140.575 315.71,142.06 U15.5@315.71,142.09
  Top Layer w0.6: v2(339.4,145.925) U7.3@339.4,147.325
  GND w0.4: v1(325.525,149.155) v1@335.77,149.155
  GND w0.6: v2(339.4,145.925) 339.4,147.175 344.6,152.375 357.675,152.375 362.25,156.95 v2(362.25,157.5)
  Bottom Layer w0.4: U24.3@314.375,120.85 317.325,120.85 v1(317.775,120.4) 317.775,112.425 v1(316.225,110.875) ; v1(315.145,149.155) 316.82,150.83 v1(316.82,155.825) ; v1(333.025,123.575) 332.3,122.85 332.3,121.775 333.225,120.85 U25.3@333.825,120.85 ; C75.1@362.375,165.775 361.15,167 C74.2@361.15,168.15 361.15,170.175 362.8,171.825 365.45,171.825 366.25,172.625 366.25,174.15 U3.3@365.075,175.325
  Bottom Layer w0.6: v2(362.25,157.5) 362.25,161 363.325,162.075 366.075,162.075 367.925,163.925 367.925,178.775 366.325,180.375 C76.1@363.8,180.375
  other v2: 311.825,126.375
3V3_D: C6.2 C7.2 C8.2 C9.2 C10.2 C60.2 FE1.2 SW.4 U6.1 U6.2 U8.5 U9.1 U9.19 U9.32 U9.48 U9.64 U11.1 U12.1 U13.1 U14.1 U18.2 U18.8 U19.2 U19.8 U19.15 U26.3 | length 175.8
  Top Layer w0.25: C9.2@321.245,154.05 320.495,154.8 320.495,160.95 C10.2@321.245,161.7 v1(322.375,161.7) U9.19@325.575,161.7 ; C9.2@321.275,154.05 323.75,154.05 324.9,155.2 U9.32@325.575,155.2 ; v1(332.325,171.275) 335.1,171.275 336.38,169.995 337.86,169.995 C6.2@338.65,169.205 ; U9.48@334.875,153.4 334.875,152.6 335.095,152.38 338.03,152.38 340.1,154.45 C8.2@340.68,154.45 ; C6.2@338.65,169.2 338.65,167.95 v1(338.675,167.925) 337.6,167.925 334.875,165.2 U9.1@334.875,164.5 334.875,163.3 335.475,162.7 U9.64@336.675,162.7 C60.2@340.405,162.7 ; C60.2@340.5,162.605 U8.5@340.5,164.05 ; C7.2@340.655,160.65 C7.2@340.655,160.925 C60.2@340.655,162.45
  Top Layer w0.4: v1(321.275,151.5) C9.2@321.275,154.02 ; FE1.2@340.63,148.7 340.63,147.94 v1(341.25,147.32)
  GND w0.4: v1(332.325,171.275) 341.175,180.125 SW.4@343.155,180.125
  VDD w0.25: v1(322.375,161.7) 323.925,161.7 328.275,166.05 328.275,167.225 v1(332.325,171.275) ; v1(338.675,167.925) 341.2,170.45 v1(342.9,170.45)
  Bottom Layer w0.25: U18.2@338.45,162.95 339.75,162.95 340.55,163.75 340.55,167.125 339.75,167.925 v1(338.675,167.925) ; U18.8@338.45,166.85 337.6,166.85 336.875,167.575 336.875,169.9 337.425,170.45 U19.2@338.45,170.45 ; U18.8@338.65,166.875 v1@338.65,167.875 ; v1(342.9,170.45) U19.15@344.05,170.45
  Bottom Layer w0.4: v1(321.275,151.5) 321.275,148.95 315.075,142.75 312.65,142.75 311.45,141.55 U14.1@311.45,139.85 311.45,138.875 312.2,138.125 317.35,138.125 318.175,138.95 318.175,138.9 318.95,138.125 324.05,138.125 324.9,138.975 325.8,138.075 331.025,138.075 331.625,138.675 332.225,138.075 336.475,138.075 338.475,140.075 U6.2@338.475,144.825 U6.1@340.375,144.825 341.25,145.7 v1(341.25,147.32) 341.25,151.1 339.935,152.415 U26.3@338.825,152.415 ; v1(332.325,171.275) 335.4,174.35 U19.8@338.45,174.35
  other v1: 338,152.425
3V3_D_GND: C1.1 C2.1 C3.2 C4.2 C5.2 C6.1 C7.1 C8.1 C9.1 C10.1 C60.1 D4.3 D4.4 FE3.2 R1.1 R2.1 R3.2 R5.2 SW.1 U6.3 U9.18 U9.63 U11.4 U12.4 U13.4 U14.4 U26.2 U27.5 U27.8 U28.3 U29.3 | length 177.3
  Top Layer w0.25: FE3.2@317.7,154.05 C9.1@319.705,154.05 C2.1@319.705,155.7 C10.1@319.705,161.7 319.725,161.7 320.5,162.475 322.85,162.475 323.125,162.2 U9.18@325.575,162.2 ; C3.2@326.35,170.77 C4.2@327.975,170.77 ; C4.2@327.975,170.745 C4.2@327.975,170.77 ; C4.2@328,170.77 C4.2@327.975,170.77 ; U9.63@336.675,162.2 337.625,162.2 339.875,159.95 341.145,159.95 R1.1@342.19,158.905 ; D4.3@341.45,174.51 342.1,175.16 342.1,177.15 343.075,178.125 348.775,178.125 SW.1@350.775,180.125 ; R3.2@342.16,155.9 v1(342.16,156.4)
  Top Layer w0.4: v1@315.25,139.125 v1(328.7,139.125) v1(335.45,139.125) ; v1(315.725,152.5) 316.12,152.5 FE3.2@317.725,154.105 ; C4.2@327.975,170.745 328,170.77 329.165,171.935 336.16,171.935 337.35,170.745 C6.1@338.65,170.745 339.75,171.845 339.75,173.81 D4.4@340.45,174.51 D4.3@341.45,174.51 342.17,173.79 R2.1@342.17,166.975 343.875,165.27 343.875,164.13 C60.1@342.195,162.45 C7.1@342.195,160.925 R1.1@342.195,158.9 ; v1(338.05,151.125) 339.05,151.125 339.4,151.475 R5.2@340.62,151.475 340.669,151.475 C1.1@342.119,152.925 ; C1.1@342.16,152.81 R3.2@342.16,155.9 ; v1(342.16,156.4) R1.1@342.16,158.865 ; C8.1@342.195,154.45 356.35,154.45 v1(357.325,153.475)
  GND w0.4: v1(315.25,139.15) 312.775,141.625 312.775,149.55 v1(315.725,152.5) 322.575,152.5 323.175,151.9 337.275,151.9 v1(338.05,151.125)
  Bottom Layer w0.4: U26.2@338.825,151.145 339.93,151.145 340.525,150.55 340.525,148.7 339.425,147.6 U6.3@339.425,147.325 ; U27.8@343.9,156.025 342.535,156.025 v1(342.16,156.4) 342.16,158.935 343.06,159.835 U27.5@343.9,159.835
  Bottom Layer w0.6: v1(357.325,153.475) 357.875,152.925 U29.3@359.125,152.925 U28.3@362.7,152.925
  other v1: 321.975,139.15
5V: "Abs Encoder.1" "P torque.1" C30.2 C40.2 C50.2 C61.2 C73.1 C74.1 C75.2 C140.2 C153.2 D11.A Hall_Sensor.1 Increase_Encoder.1 L1.1 Q7.2 R70.2 R72.2 R73.2 R75.2 R78.2 Rp1.5 Rp1.6 Rp1.7 Rp2.5 Rp2.6 Rp2.7 Rp4.5 Rp4.6 Rp4.7 Rp4.8 Rp5.5 Rp5.6 Rp5.7 Rp5.8 U3.1 U5.1 U5.2 U11.8 U12.8 U13.8 U14.8 U15.1 U16.1 U17.1 U18.15 | length 404.5
  Top Layer w0.4: 305.5,152.05 307.375,152.05 309.405,154.08 C140.2@315.375,154.08 ; C30.2@310.385,130.6 310.385,130.965 309.425,131.925 309.425,133.25 308.85,133.825 U15.1@308.09,133.825 308.09,134.865 309.8,136.575 316.575,136.575 318.515,134.635 320.43,136.55 327.1,136.55 328.99,134.66 330.88,136.55 v2@336.35,136.55 ; U16.1@318.515,133.75 319.6,133.75 320.05,133.3 320.05,131.825 C40.2@320.835,131.04 ; U17.1@328.99,133.75 329.8,133.75 330.425,133.125 330.425,131.725 C50.2@331.285,130.865 ; 333.65,177.475 333.65,180.125 336.95,183.425 345,183.425 346.775,181.65 351.45,181.65 v1@353.525,179.575 ; C61.2@346.005,159.125 346.005,157.37 Hall_Sensor.1@346.575,156.8 ; R78.2@349.264,174.505 346.625,171.866 Increase_Encoder.1@346.625,167.25 349.225,164.65 349.225,163.42 Rp1.6@349.95,163.42 Rp1.5@350.9,163.42 351.155,163.42 v2(351.95,162.625) ; v2@352.027,162.702 352.85,161.88 Rp2.5@352.975,161.88 Rp2.6@353.925,161.88 Rp2.7@354.6,161.88
  Top Layer w0.6: v2@323.105,109.725 Rp5.5@323.105,104.4 Rp5.6@323.105,103.45 Rp5.7@323.105,102.65 Rp5.8@323.105,101.7 322.225,100.82 322.225,100.025 323.275,98.975 D11.A@325.28,98.975 ; 333.65,177.475 333.65,176.775 334.025,176.4 v1(334.675,176.4)
  VDD w0.4: Hall_Sensor.1@346.575,156.8 Hall_Sensor.1@346.575,157.25
  VDD w0.6: 305.5,152.05 308.975,152.05 313.575,156.65 313.575,162.225 334.225,182.875 346.1,182.875 347.25,181.725 351.35,181.725 353.5,179.575 v1(353.5,179.55) 353.5,177.175 359.475,171.2 v2(359.475,167.775) ; v2@323.105,109.725 323.105,110.905 327.6,115.4 338.75,115.4 345.7,122.35 345.7,125.925 ; v2@336.225,136.525 336.375,136.675 336.375,145.9 344.675,154.2 348.7,154.2 350.375,155.875 350.375,158.975 354.75,163.35 v2(359.5,163.35) ; Hall_Sensor.1@346.575,157.25 v2(351.95,162.625) 355.225,165.9 v2(359.475,165.9) ; v2(348.175,125.925) 345.7,125.925 ; v2(361.475,163.3) 359.925,161.75 355.525,161.75 352.875,159.1 352.875,154.75 350.5,152.375 344.492,152.375 337.525,145.408 337.525,134.1 345.7,125.925
  Bottom Layer w0.25: U18.15@344.05,162.95 343.075,162.95 342.1,163.925 342.1,167.175 343.2,168.275 344.425,168.275 345.45,167.25 Increase_Encoder.1@346.625,167.25
  Bottom Layer w0.4: U14.8@311.45,134.75 311.45,135.675 312.35,136.575 317.2,136.575 318.175,135.6 319.125,136.55 324,136.55 324.9,135.65 324.9,135.5 325.975,136.575 330.7,136.575 U11.8@331.625,135.65 ; U11.8@331.625,134.75 U11.8@331.625,135.65 ; v2(336.35,136.525) 332.5,136.525 U11.8@331.625,135.65
  Bottom Layer w0.6: U5.2@335.125,176.4 U5.1@337.025,176.4 ; Q7.2@340.925,122.875 347.17,122.875 C153.2@347.175,122.87 347.175,125.45 ; R70.2@344.975,126.345 346.28,126.345 347.175,125.45 ; v2(348.175,125.925) 347.7,125.45 347.175,125.45
  other v1: 363.775,163.4 364.7,163.4
  other v2: 323.05,109.725
15V: C24.2 C70.1 C71.2 Cff.2 Cout.1 R12.1 R13.1 R14.1 R77.2 Rfbt.2 U1.7 U2.7 U4.1 U4.2 U10.1 | length 139.3
  Top Layer w0.4: R77.2@353.075,174.455 354.77,176.15 v1(356.325,176.15)
  Top Layer w0.6: C24.2@328.765,111.75 U10.1@331,111.75
  Top Layer w0.8: C24.2@328.39,112.125 328.39,113.815 v2(328.875,114.3) 329.65,115.075 U4.1@329.65,116.025 U4.2@329.65,117.925 ; U1.7@367.015,163.575 367.015,167.235 367.48,167.7 Cff.2@367.48,169.95 367.48,170.63 v2(369.25,172.4) ; C71.2@369.775,176.35 371.725,178.3 371.75,178.275 v2(373.05,178.275)
  GND w0.8: v2(363.875,160.35) 363.875,154.3 365.525,152.65 v2@365.525,130.75
  VDD w0.8: v2(328.875,114.3) 339.275,114.3 351.375,126.4 362.775,126.4 365.475,129.1 v2(365.475,130.8) ; v1(356.325,176.15) 360.075,172.4 v2(369.25,172.4) 373.05,176.2 v2(373.05,178.275)
  Bottom Layer w0.8: R14.1@328.855,97.925 v2@328.855,114.28
A_GND: "Abs Encoder.6" "Abs Encoder.7" "P torque.4" Brake.2 C24.1 C30.1 C32.1 C33.1 C40.1 C42.1 C43.1 C50.1 C52.1 C53.1 C61.1 C62.1 C63.1 C64.1 C65.1 C66.1 C67.1 C70.2 C71.1 C73.2 C91.1 C92.1 C93.1 C94.1 C95.1 C96.1 C97.1 C140.1 C151.1 C152.1 C153.1 Cin1.2 Cin2.2 Cin.1 Co2.1 Co4.1 Co6.1 Cout.2 Css.1 D1.K D2.K D3.K D6.1 D8.1 D10.1 FE2.2 Hall_Sensor.5 Increase_Encoder.5 R26.1 R27.1 R28.1 R31.1 R32.1 R33.1 R35.1 R45.1 R55.1 R76.1 Renb.1 Rfbb.1 T1.1 U1.4 U1.8 U2.6 U2.9 U4.3 U5.3 U10.12 U10.13 U11.5 U12.5 U13.5 U14.5 U15.4 U16.4 U17.4 U18.9 U19.9 U20.3 U21.2 U21.8 U21.10 Vin_I.1 Vin_II.1 | length 723.3
  Top Layer w0.2: v1@342.675,176.709 342.675,174.975 343.195,174.455 D3.K@343.625,174.455 343.705,174.455 344.935,173.225 346.131,173.225 D2.K@347.436,174.53 347.555,174.53 348.255,175.23 350.497,175.23 D1.K@351.247,174.48 D1.K@351.247,174.103 ; C65.1@347.805,169.5 348.755,170.45 350.03,170.45 C66.1@350.98,169.5 351.855,170.375 353.33,170.375 C67.1@354.205,169.5 355.03,170.325 356.55,170.325 356.785,170.09 Increase_Encoder.5@356.785,167.25 ; C62.1@349.238,159.125 C61.1@347.545,159.125 347.585,159.085 347.585,156.515 348.425,155.675 349.8,155.675 350.5,156.375 ; C63.1@352.472,159.125 350.5,157.153 350.5,156.375 ; C64.1@355.705,159.125 354.78,158.2 353.95,158.2 353,157.25 353,156.375 ; Hall_Sensor.5@356.735,156.8 355.685,155.75 353.625,155.75 353,156.375 ; 350.5,156.375 351.2,155.675 352.3,155.675 353,156.375
  Top Layer w0.25: v1(302.825,128.925) C94.1@302.825,130.105 ; C95.1@320.995,109.725 322.17,110.9 325.385,110.9 C24.1@326.61,112.125 ; U10.12@331,97.78 329.48,97.78 328.825,97.125 328.825,94.95 331.05,92.725 342.53,92.725 C96.1@344.655,94.85 ; FE2.2@342.16,150.1 345.36,153.3 v1(345.65,153.3) ; C97.1@379.85,109.77 382.945,109.77 385.95,112.775 v1(385.95,113.575)
  Top Layer w0.4: 308.72,158.956 312.056,155.62 C140.1@315.375,155.62 ; C30.1@313.365,130.6 313.365,130.89 314.4,131.925 314.4,133.45 314.775,133.825 U15.4@315.71,133.825 ; R35.1@316.07,127.875 v1@316.07,128.72 ; v2(316.25,135.325) 315.71,134.785 U15.4@315.71,133.825 ; C43.1@318.7,131.445 315.92,131.445 315.71,131.655 U15.4@315.71,133.825 ; C40.1@323.815,130.6 323.815,130.865 324.75,131.8 324.75,133.25 325.25,133.75 U16.4@326.135,133.75 326.135,131.68 326.395,131.42 C53.1@329.2,131.42 ; R45.1@326.47,127.875 v1@326.47,128.73 ; U10.13@331,96.51 333.515,96.51 335.075,94.95 v4(335.075,95.075) ; C50.1@334.265,130.84 335.075,131.65 335.075,133.05 335.775,133.75 U17.4@336.61,133.75 C52.1@336.61,131.805 ; U21.2@336.815,115.84 337.7,116.725 340.333,116.725 349.783,126.175 356.375,126.175 361.175,130.975 Cin2.2@361.775,130.975 ; R55.1@336.945,127.875 v1@336.945,128.73 ; 337.825,176.675 v1(337.825,178.9) ; C92.1@356.87,184.4 v1@357.9,184.4 ; R76.1@363.5,164.7 363.825,165.025 363.825,168.55 364.175,168.9
  Top Layer w0.6: C33.1@308.175,131.495 308.43,131.495 v1(309.05,130.875) ; C93.1@322.695,173.675 324.725,173.675 ; C24.1@326.61,112.125 326.61,114.385 327.15,114.925 U4.3@327.15,116.975 327.15,117.051 328.924,118.825 331.275,118.825 332.8,117.3 ; U10.12@331,97.78 334.855,97.78 v2(335.275,98.2) ; v1@332.8,112.025 332.8,117.3 ; U21.10@334.275,124.325 334.275,121.7 335.15,120.825 ; U21.2@336.815,114.765 U21.2@336.815,115.84 ; U21.8@339.355,124.325 339.355,121.7 338.48,120.825 335.15,120.825 ; D1.K@351.247,174.103 v1(352.1,173.25) ; Rfbb.1@373.66,171.8 C91.1@375.93,171.8 ; 332.8,117.3 335.15,119.65 335.15,120.825
  Top Layer w0.8: U1.8@370.825,156.175 U1.4@370.825,163.575 370.825,165.875 372.15,167.2 372.15,167.962 373.645,169.457 Css.1@373.645,169.75 373.645,174.105 373,174.75 C70.2@371.725,174.75
  GND w0.25: v1@345.65,153.175 345.65,154.2
  GND w0.4: 308.72,158.956 308.684,158.993 308.684,163.434 309.975,164.725 316.55,164.725 325.45,173.625 v1(326.55,173.625) ; v4(335.075,95.075) 335.075,94.95 336.55,93.475 353.3,93.475 355.25,95.425 355.25,102.675 ; v1(344.05,167.525) 346.325,169.8 348.9,169.8 351,171.9 351,173.25
  GND w0.6: v1(309.05,130.875) 311.375,128.55 315.9,128.55 v1(316.1,128.75) 316.25,128.9 v2(316.25,135.325) 322.325,135.325 326.45,131.2 v1(326.45,128.75) ; 326.55,130.975 327,131.425 334.375,131.425 v2(335.05,132.1) ; v1(326.55,173.625) 327.675,173.625 v1(328.65,172.65) 330.95,170.35 333.05,170.35 336.775,174.075 350.175,174.075 351,173.25 v1(352.1,173.25) 363.55,173.25 v1(365.95,170.85) ; v1(336.925,128.75) 336.925,130.225 v2(335.05,132.1) ; Hall_Sensor.5@356.735,156.8 356.785,156.85 Increase_Encoder.5@356.785,167.25 359.185,169.65 v1(365.95,169.65) ; v1(366.025,168.475) 362.65,165.1 362.65,160.375 356.475,154.2 344.65,154.2 337.075,146.625 337.075,139.1 335.05,137.075 v2(335.05,132.1)
  GND w4: 352.1,102.675 355.25,102.675 356.9,104.325 356.9,111.3 355.375,112.825 ; 352.225,112.825 355.375,112.825 ; 352.275,123.025 353.55,123.025 ; 362.725,133.85 362.725,132.2 353.55,123.025 ; 353.55,123.025 354.325,123.025 357.25,120.1 357.25,114.7 355.375,112.825
  VDD w0.25: v1(302.825,128.925) 304.775,130.875 v1(309.05,130.875)
  VDD w0.6: v1(332.775,112.025) 334.025,113.275 339.775,113.275 351.8,125.3 363.625,125.3 366.725,128.4 v2(366.725,129.375)
  Bottom Layer w0.2: v1(332.775,112.025) 334.05,112.025 335.1,113.075 335.1,114.45 337.09,116.44 341.21,116.44 C152.1@342.875,118.105
  Bottom Layer w0.25: v1(342.692,176.709) 342.692,174.933 343.275,174.35 U19.9@344.05,174.35
  Bottom Layer w0.4: v2(327.975,131.425) 328.71,132.16 U12.5@328.71,134.75 ; v2(335.05,132.1) 335.05,133 335.435,133.385 U11.5@335.435,134.75 ; U5.3@336.075,178.9 v1(337.825,178.9) U20.3@339.8,178.9 ; C152.1@342.875,118.105 346.055,118.105 347.175,119.225 C153.1@347.175,121.33 ; U18.9@344.05,166.85 v1(344.05,167.525) ; v1(357.95,184.4) 360.9,184.4 v1(363.975,181.325)
  Bottom Layer w0.6: U14.5@315.26,134.75 315.675,134.75 v2(316.25,135.325) ; D6.1@332.775,110.45 v1(332.775,112.025) ; D10.1@333.375,96.025 333.375,96.3 v2(335.275,98.2) 335.35,98.275 335.35,101.32 D8.1@333.375,103.295 335.35,105.27 335.35,108.59 D6.1@333.375,110.565 ; Brake.2@343.19,91.35 345.565,93.725 356.5,93.725 358.725,95.95 358.725,103.975 ; v2@366.685,129.4 366.685,140.95 ; R32.1@385.875,126.045 Co2.1@385.875,127.655 ; v1@385.945,113.58 Co6.1@385.945,115.225 ; R33.1@386.025,119.695 Co4.1@386.025,121.095
  Bottom Layer w4: R28.1@352.174,102.767 355.542,102.767 357.125,104.35 357.125,111.009 355.292,112.842 ; R27.1@352.174,112.842 355.292,112.842 ; R26.1@352.174,122.917 353.467,122.917 362.3,131.75 362.3,141.1 ; 354.408,122.917 357.225,120.1 357.225,114.775 355.292,112.842
  other v1: 386.025,120.475 385.875,126.9 385.875,132.295 372.025,155.85 369.525,155.908 370.8,155.958 372.025,156.958 369.525,157.017 372.025,158.067 369.525,158.125 372.025,159.175 369.525,159.233 336.25,173.55 325.45,176.05 324.75,177.45 326.25,177.45
  other v2: 354.225,101.35 351.175,102.85 354.25,102.85 352.75,102.875 354.175,111.9 351.55,113.65 352.825,113.675 354.325,121.925 352.8,123.575 354.325,123.6 361.375,133.825 363.45,133.85 361.375,135.297 322.225,135.325 363.45,135.322 361.375,136.769 363.45,136.794 361.375,138.241 363.45,138.266 385.6,139.6 361.375,139.713 363.45,139.738 379.95,140.025 361.375,141.175 363.45,141.2 385.6,141.436 379.95,142.3 381.625,142.3 383.375,142.325 385.6,143.496 385.6,145.557 385.6,147.618 385.6,149.679 385.6,151.739 379.95,151.925 383.425,153.8 385.6,153.8 379.925,153.825 381.6,153.825
ADC12_IN6: U9.22
ADC12_IN7: U9.23
ADC12_IN8: U9.26
ADC12_IN14: C84.2 R93.2 U9.24 | length 58
  Top Layer w0.25: v1(304.325,122.75) 304.485,122.75 C84.2@305.425,123.69 ; U9.24@325.575,159.2 326.807,159.2 v1(327.45,158.557)
  Top Layer w0.4: C84.2@305.46,123.655 R93.2@307.275,123.655
  VDD w0.25: v1(304.325,122.75) 316.5,122.75 319.425,125.675 319.425,138.45 322.1,141.125 322.1,153.207 v1(327.45,158.557)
